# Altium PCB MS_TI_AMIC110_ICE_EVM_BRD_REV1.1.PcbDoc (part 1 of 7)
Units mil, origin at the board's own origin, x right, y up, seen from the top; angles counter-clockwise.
Board outline 3464.57 x 2204.72 mil, 8 copper layers (TopLayer - S1 (.GTL), MidLayer1 - S2 (.G1), MidLayer2 - S3 (.G2), MidLayer3 - S4 (.G3), MidLayer4 - S5 (.G4), MidLayer5 - S6 (.G5), MidLayer6 - S7 (.G6), BottomLayer - S8 (.GBL)), stack 58.937 mil thick; 504 components, 369 nets, 1811 pads, 874 vias.
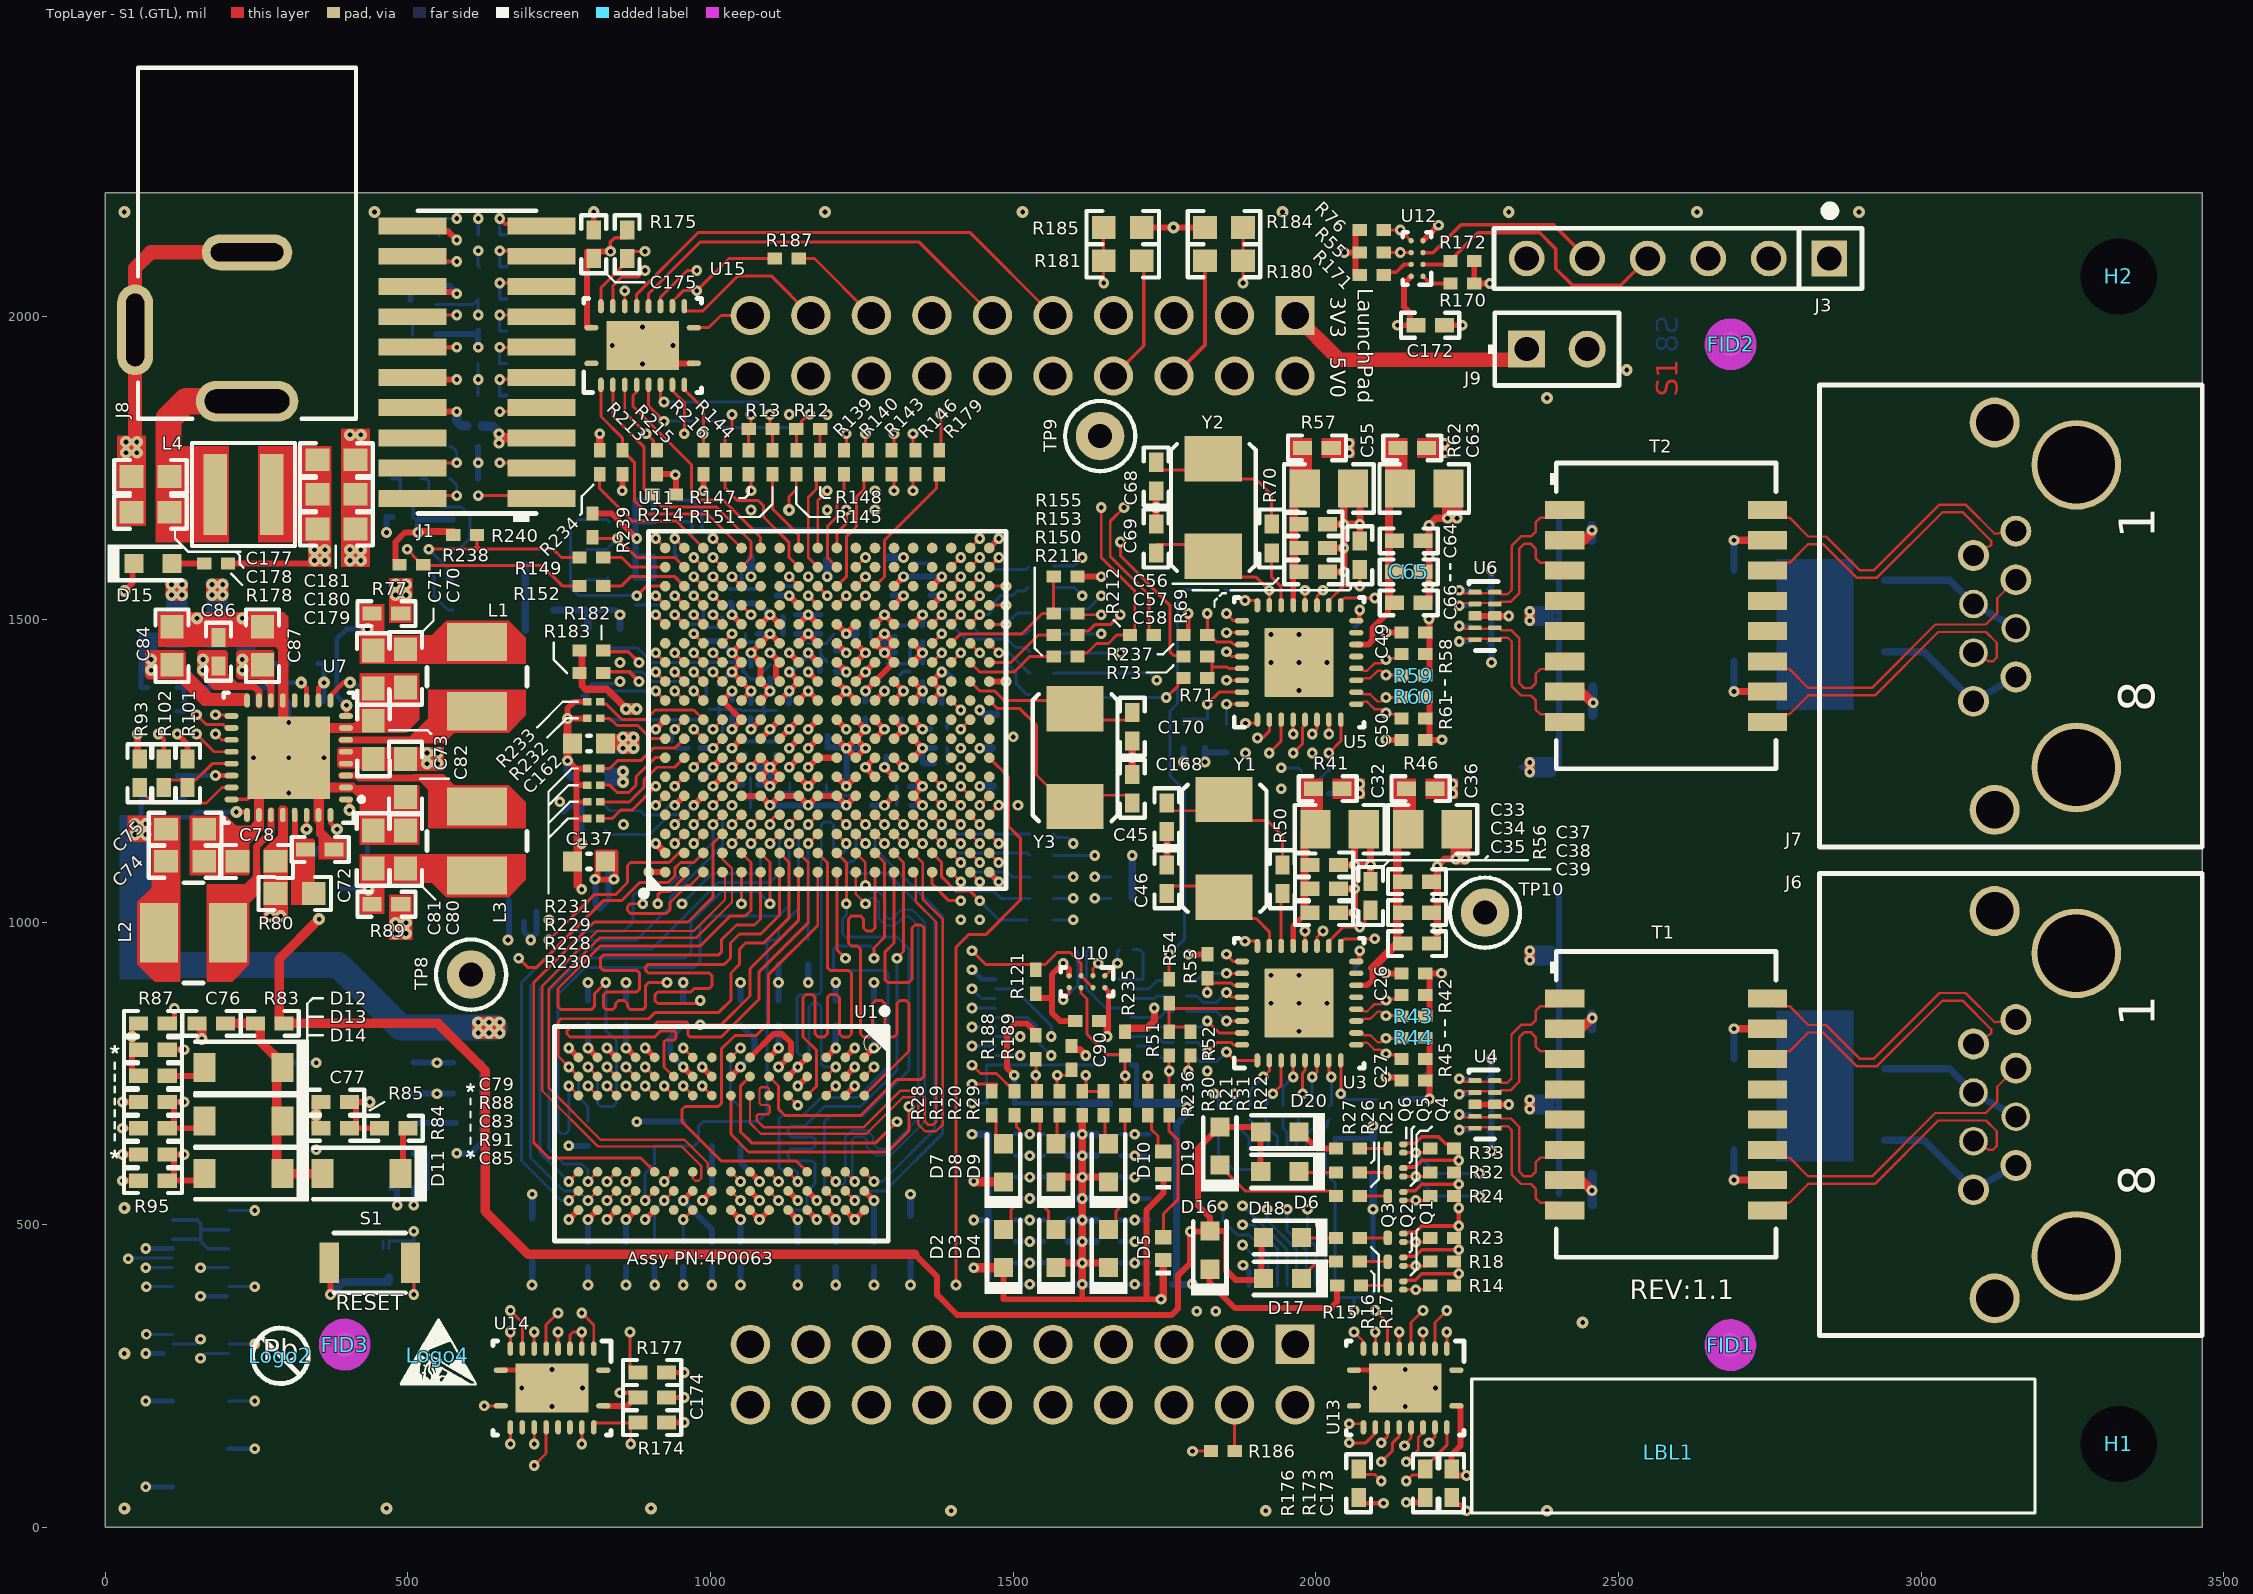
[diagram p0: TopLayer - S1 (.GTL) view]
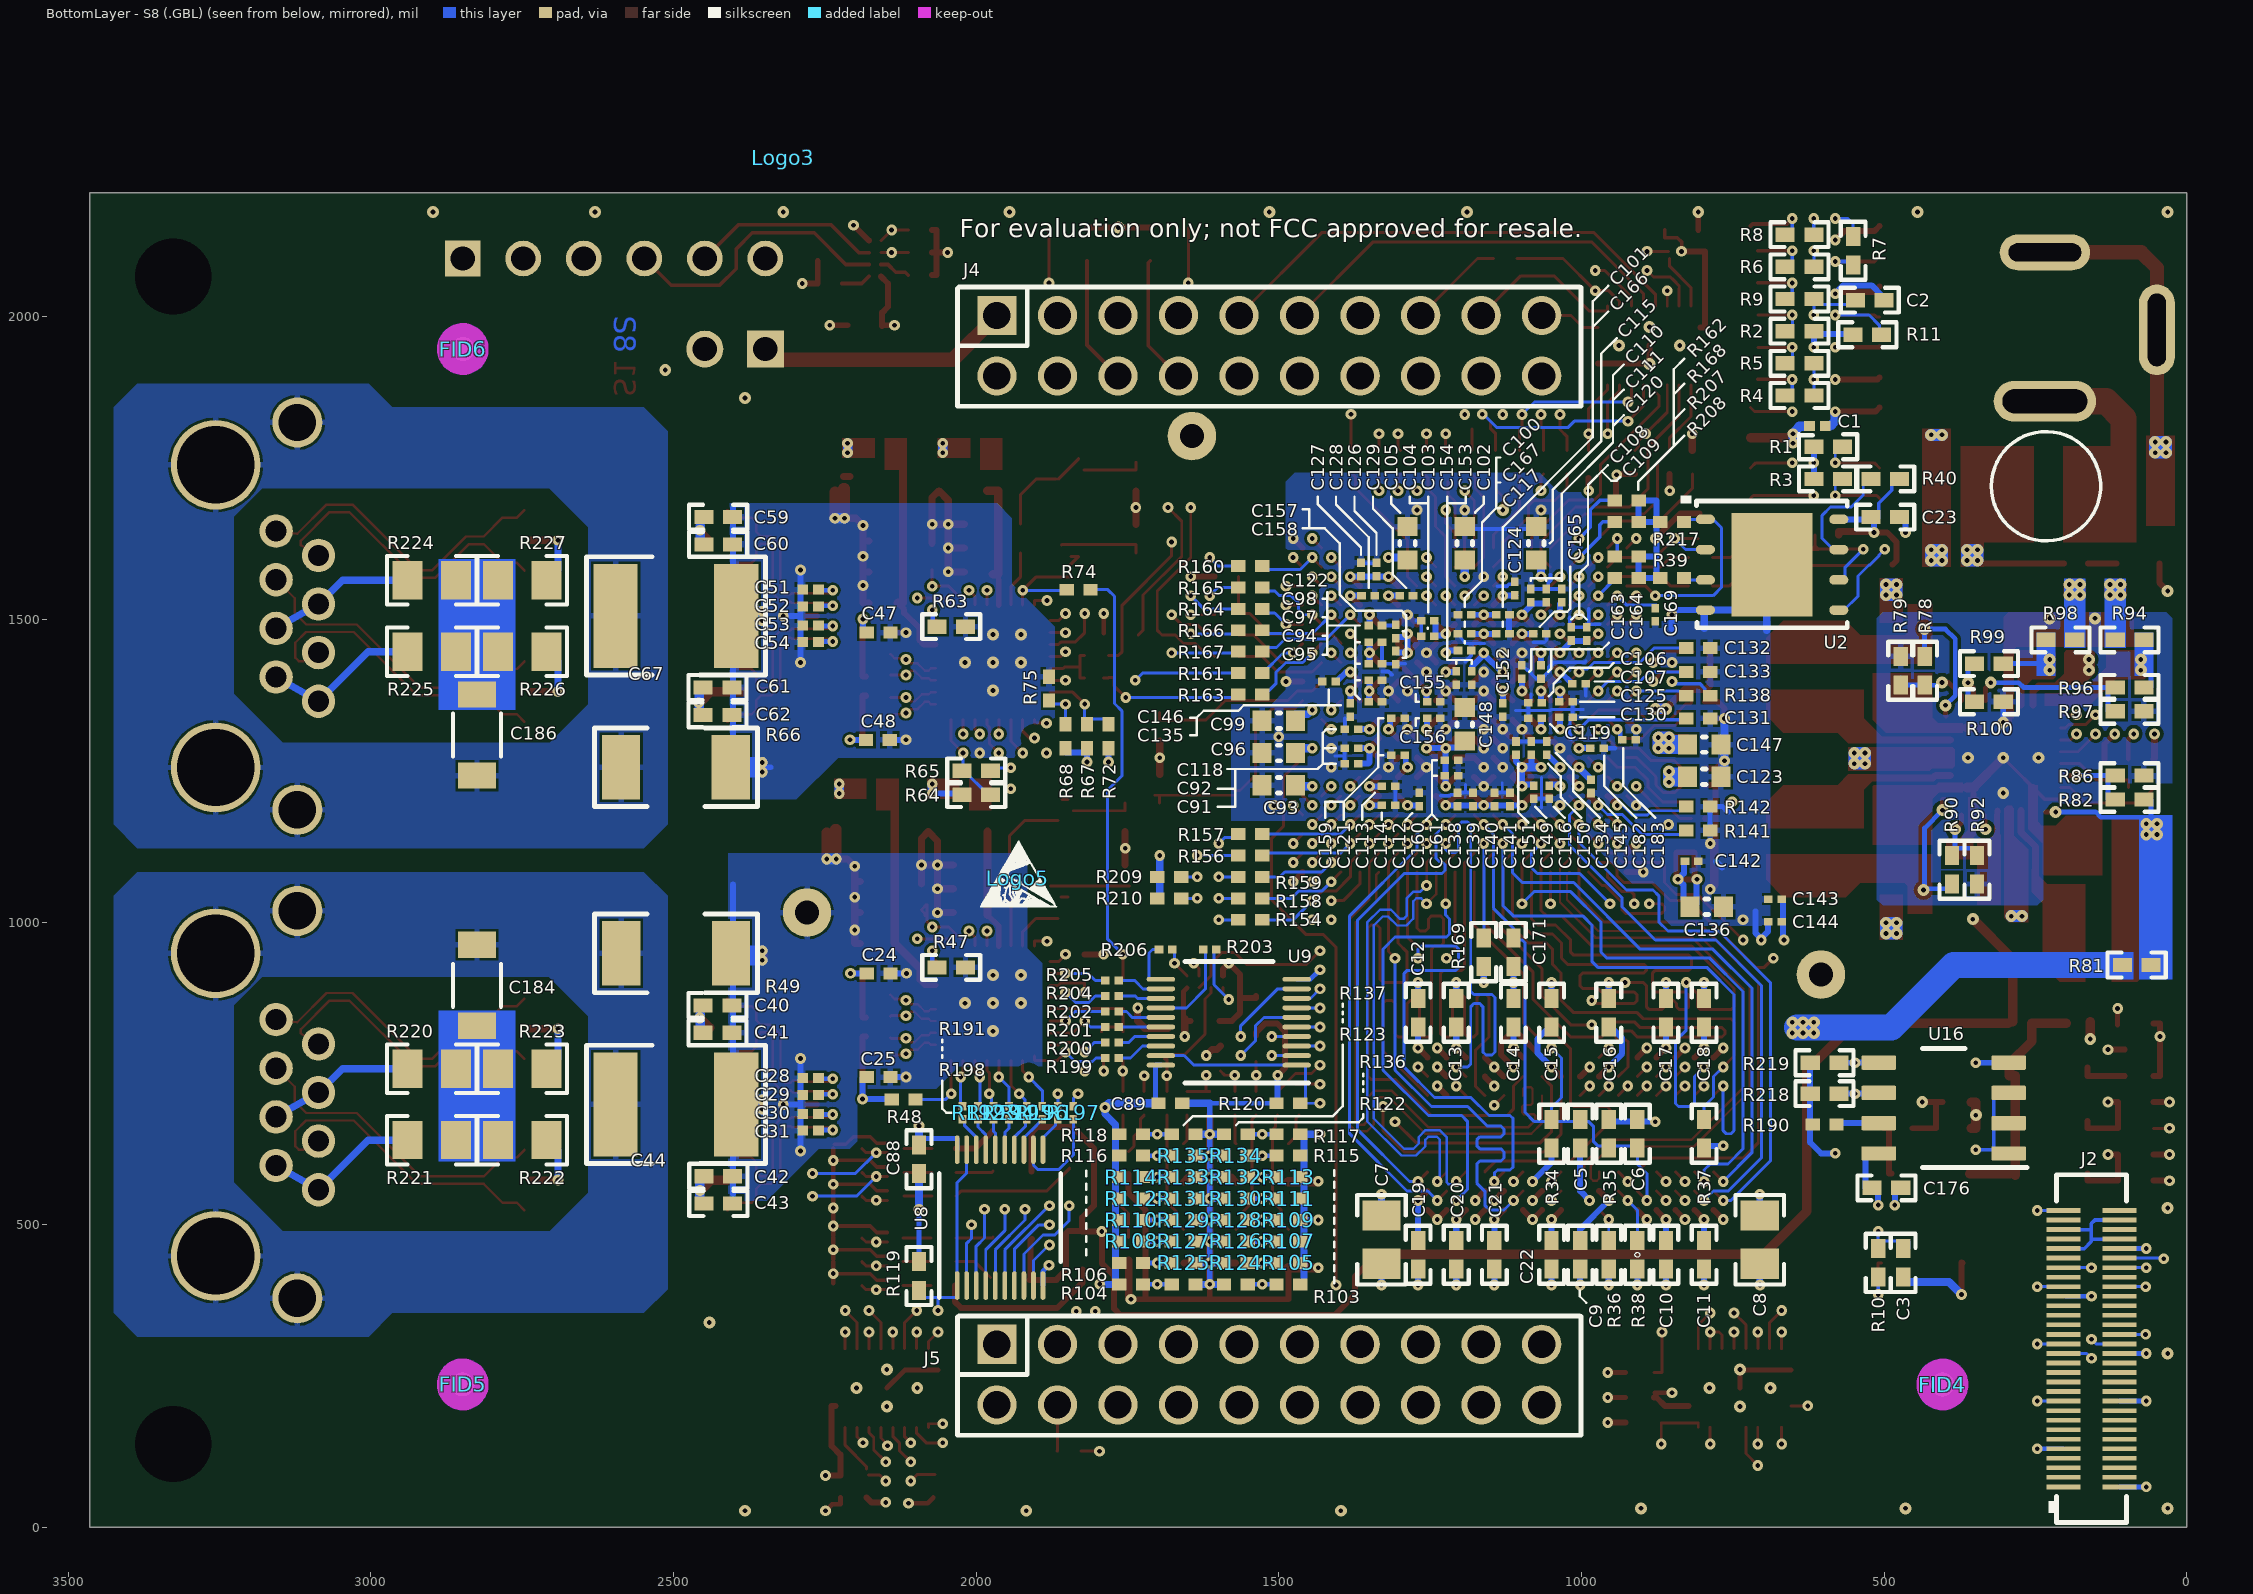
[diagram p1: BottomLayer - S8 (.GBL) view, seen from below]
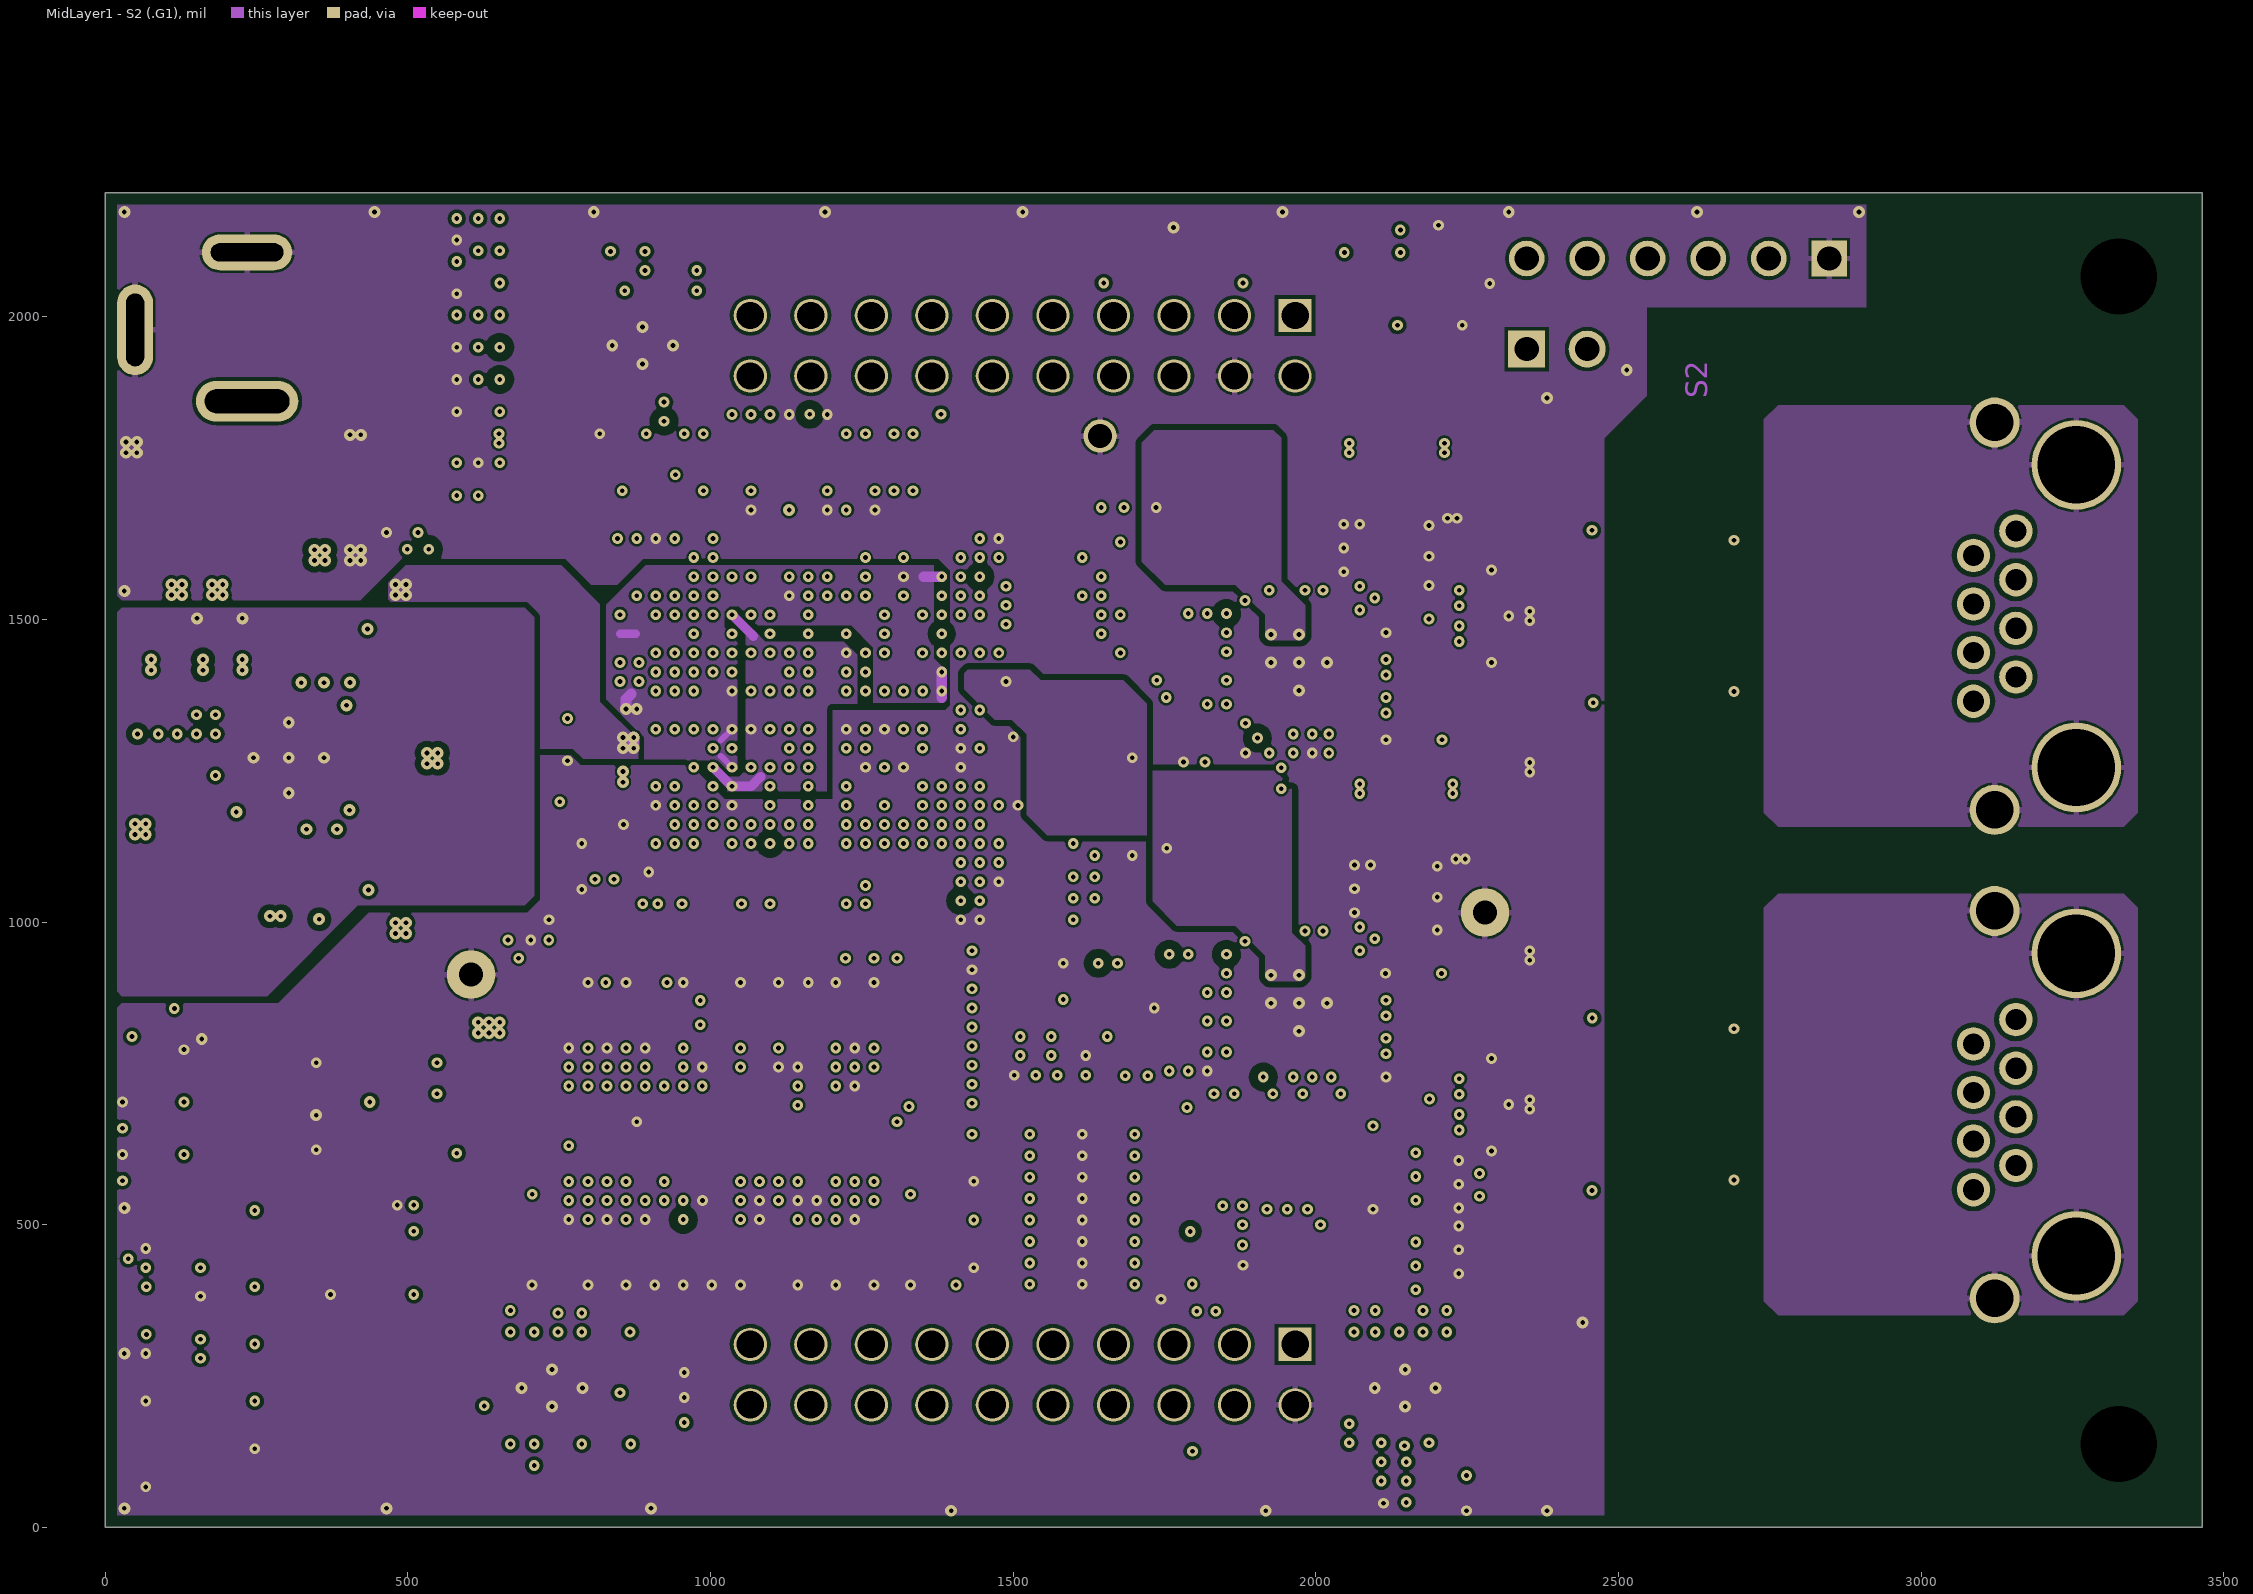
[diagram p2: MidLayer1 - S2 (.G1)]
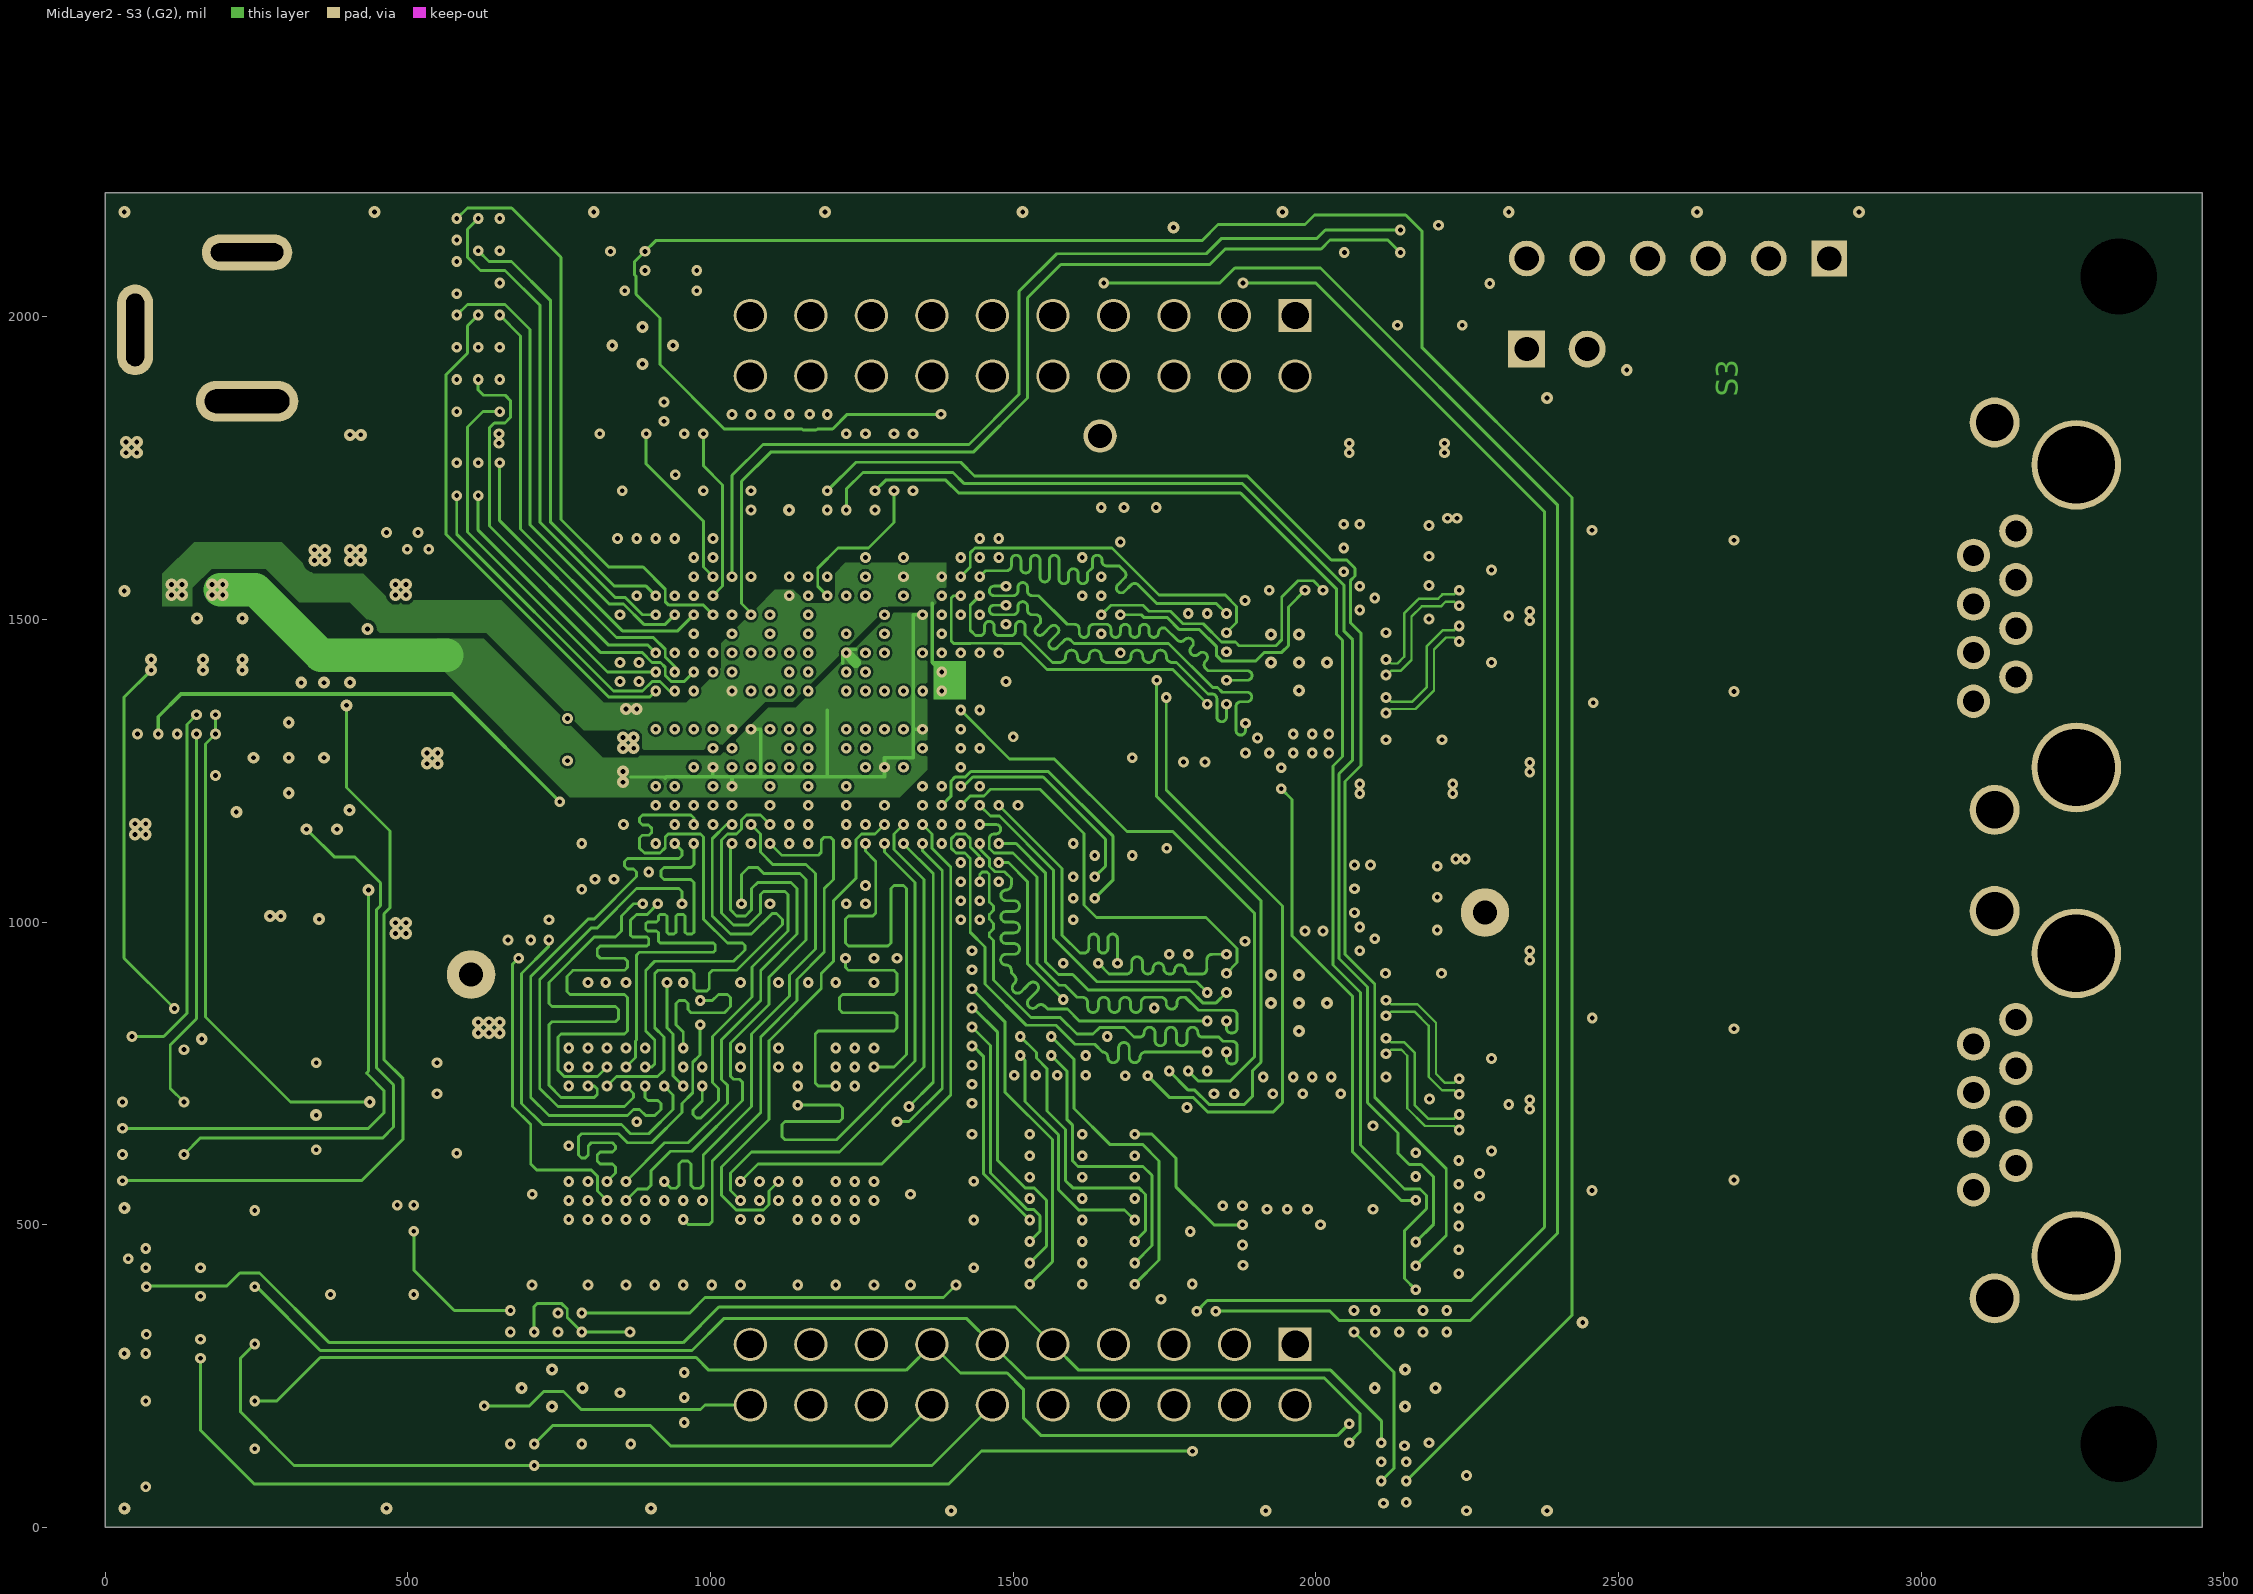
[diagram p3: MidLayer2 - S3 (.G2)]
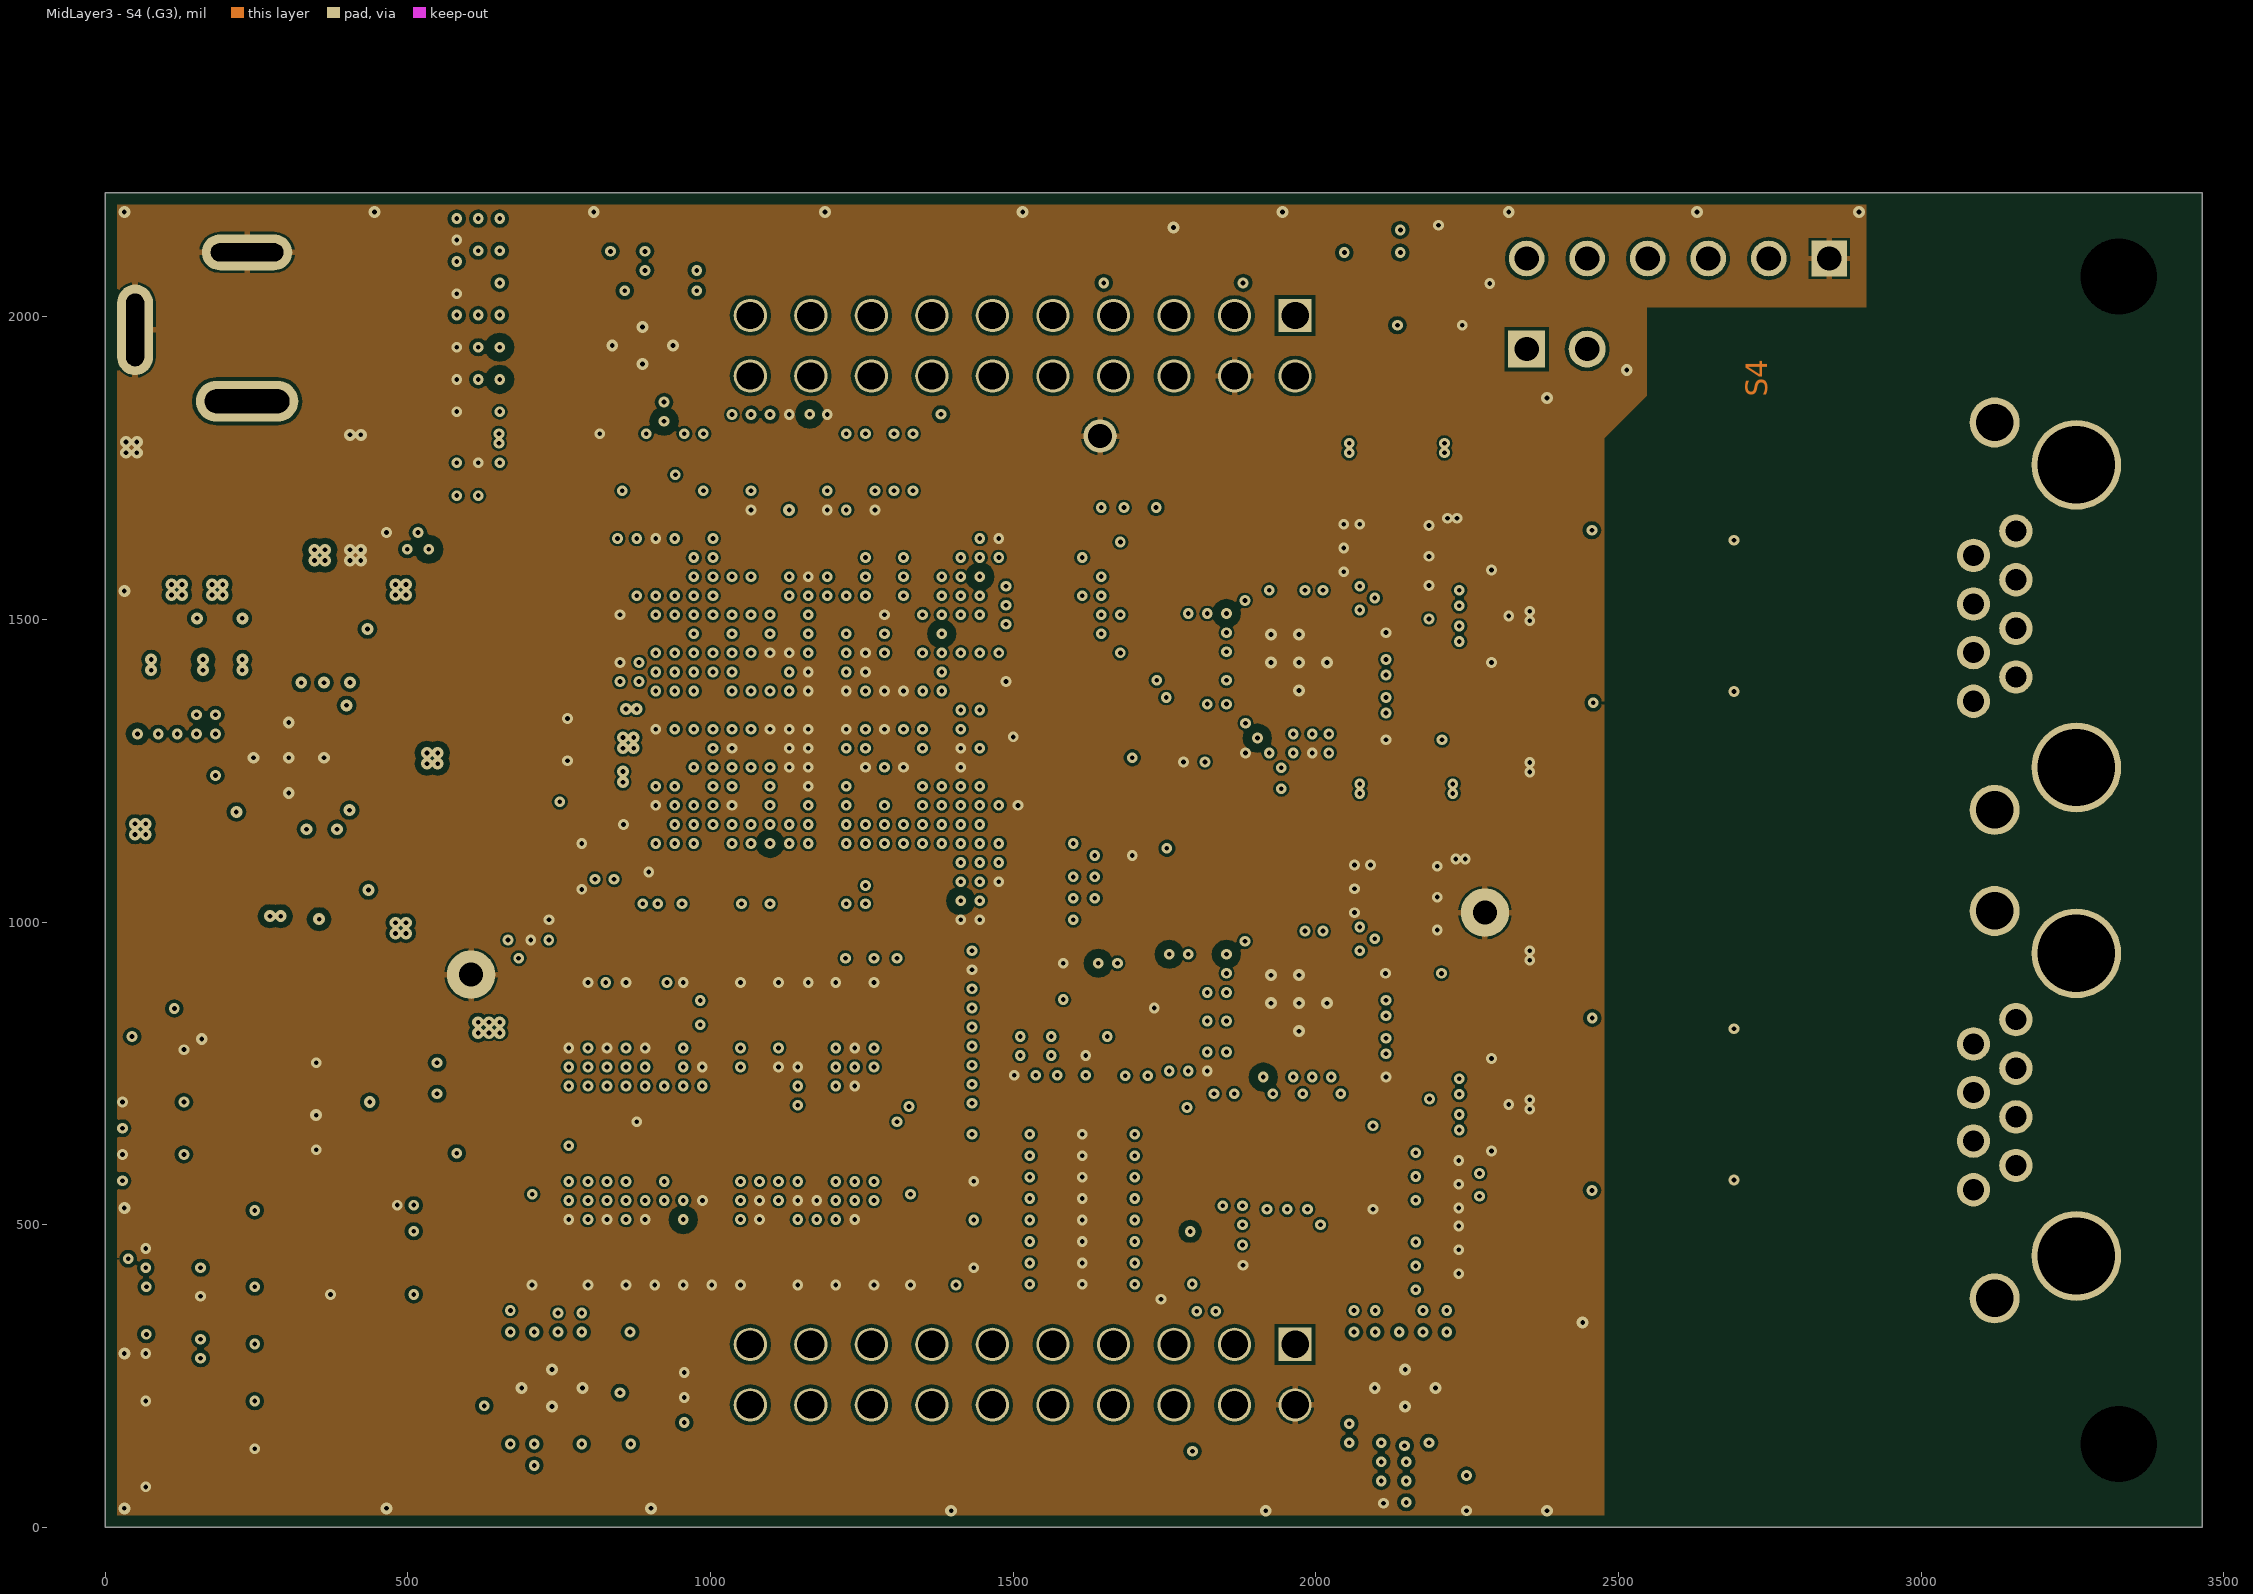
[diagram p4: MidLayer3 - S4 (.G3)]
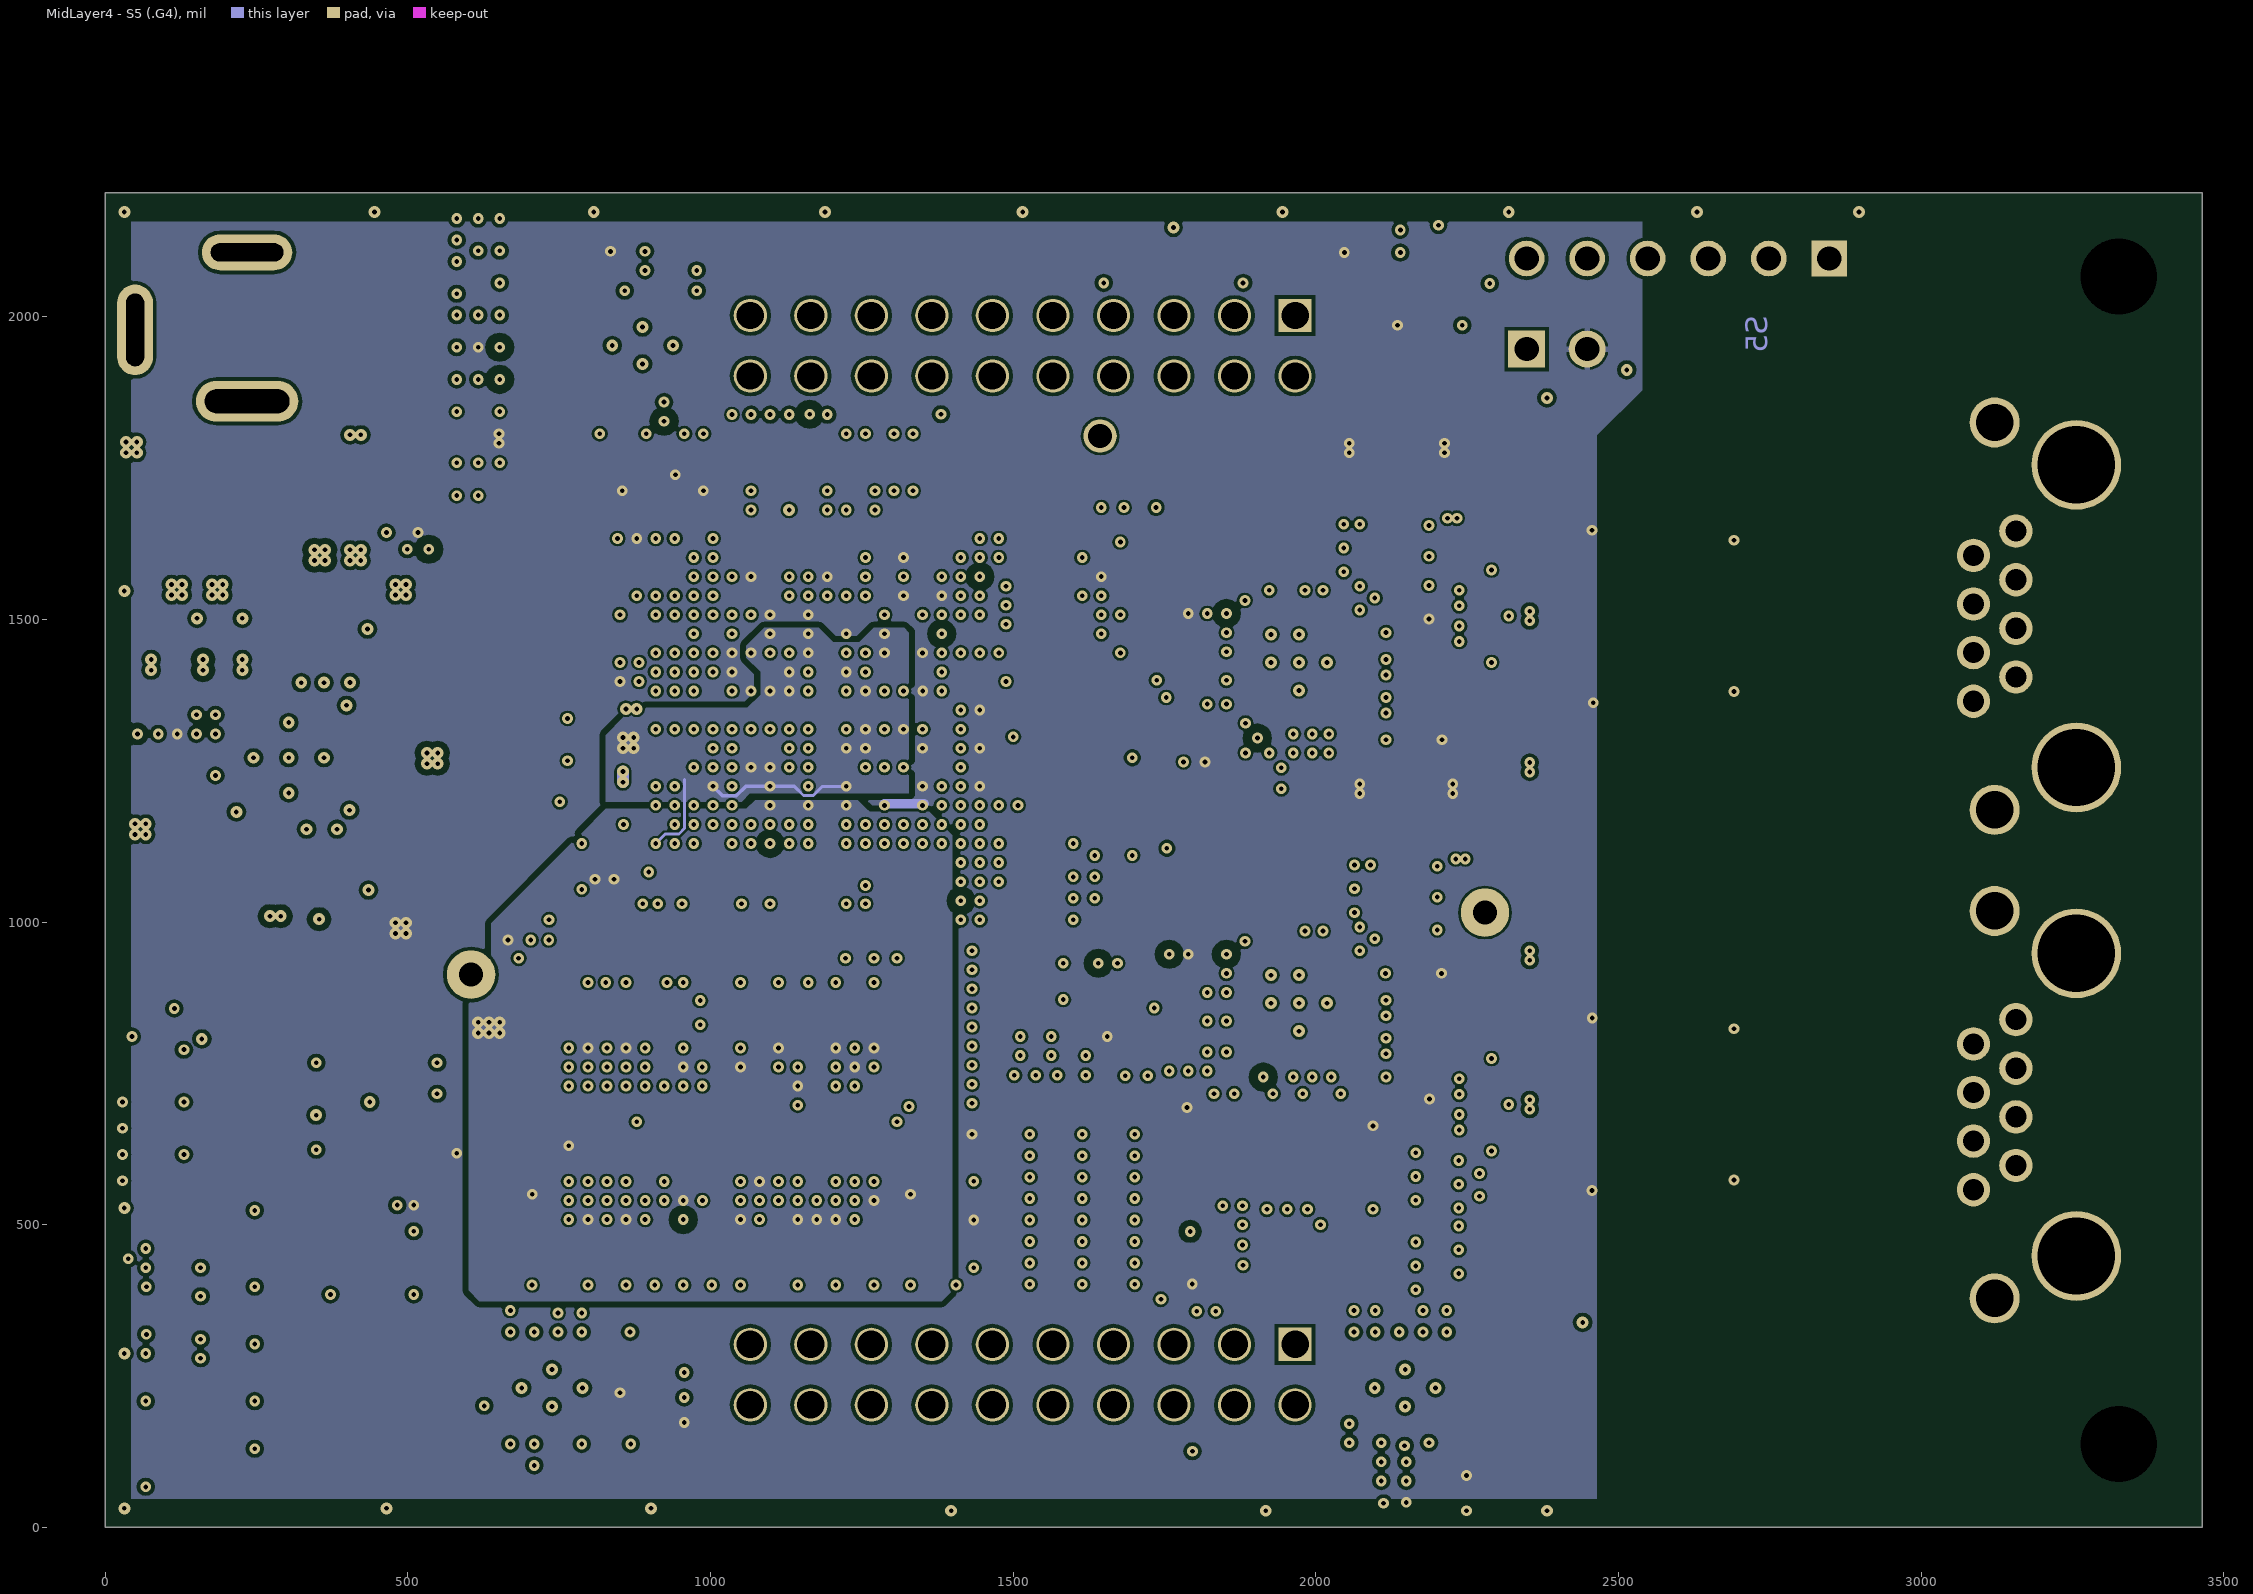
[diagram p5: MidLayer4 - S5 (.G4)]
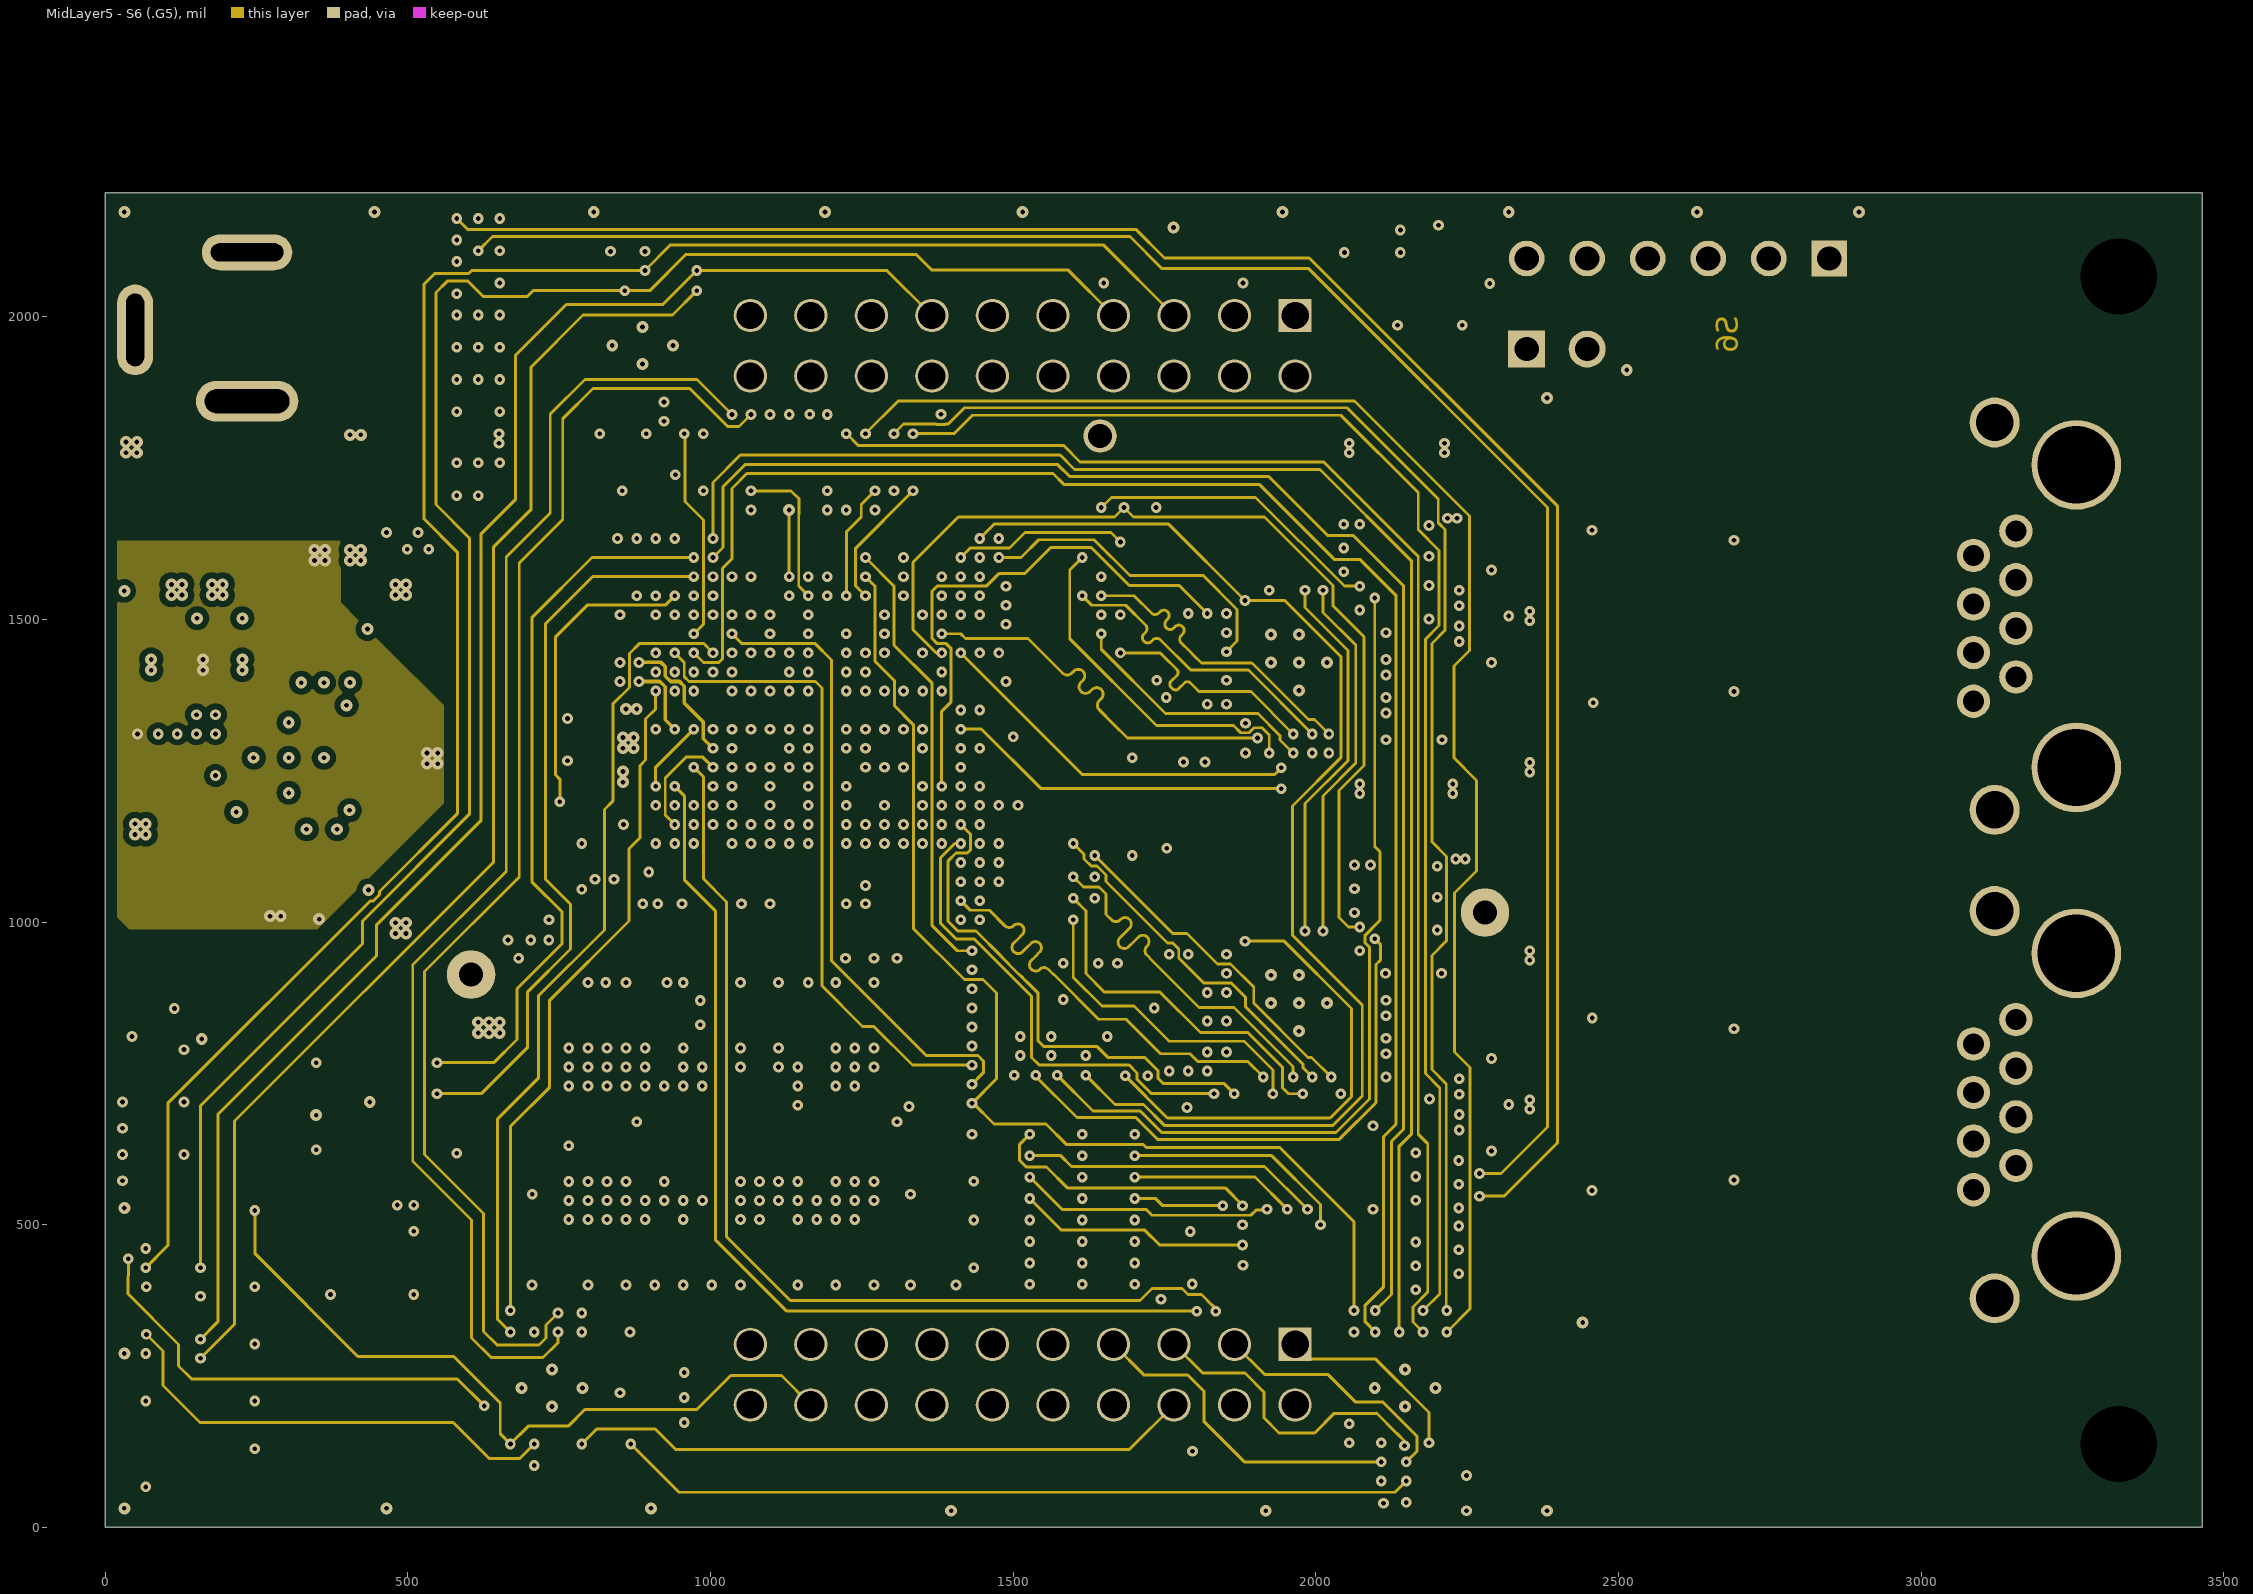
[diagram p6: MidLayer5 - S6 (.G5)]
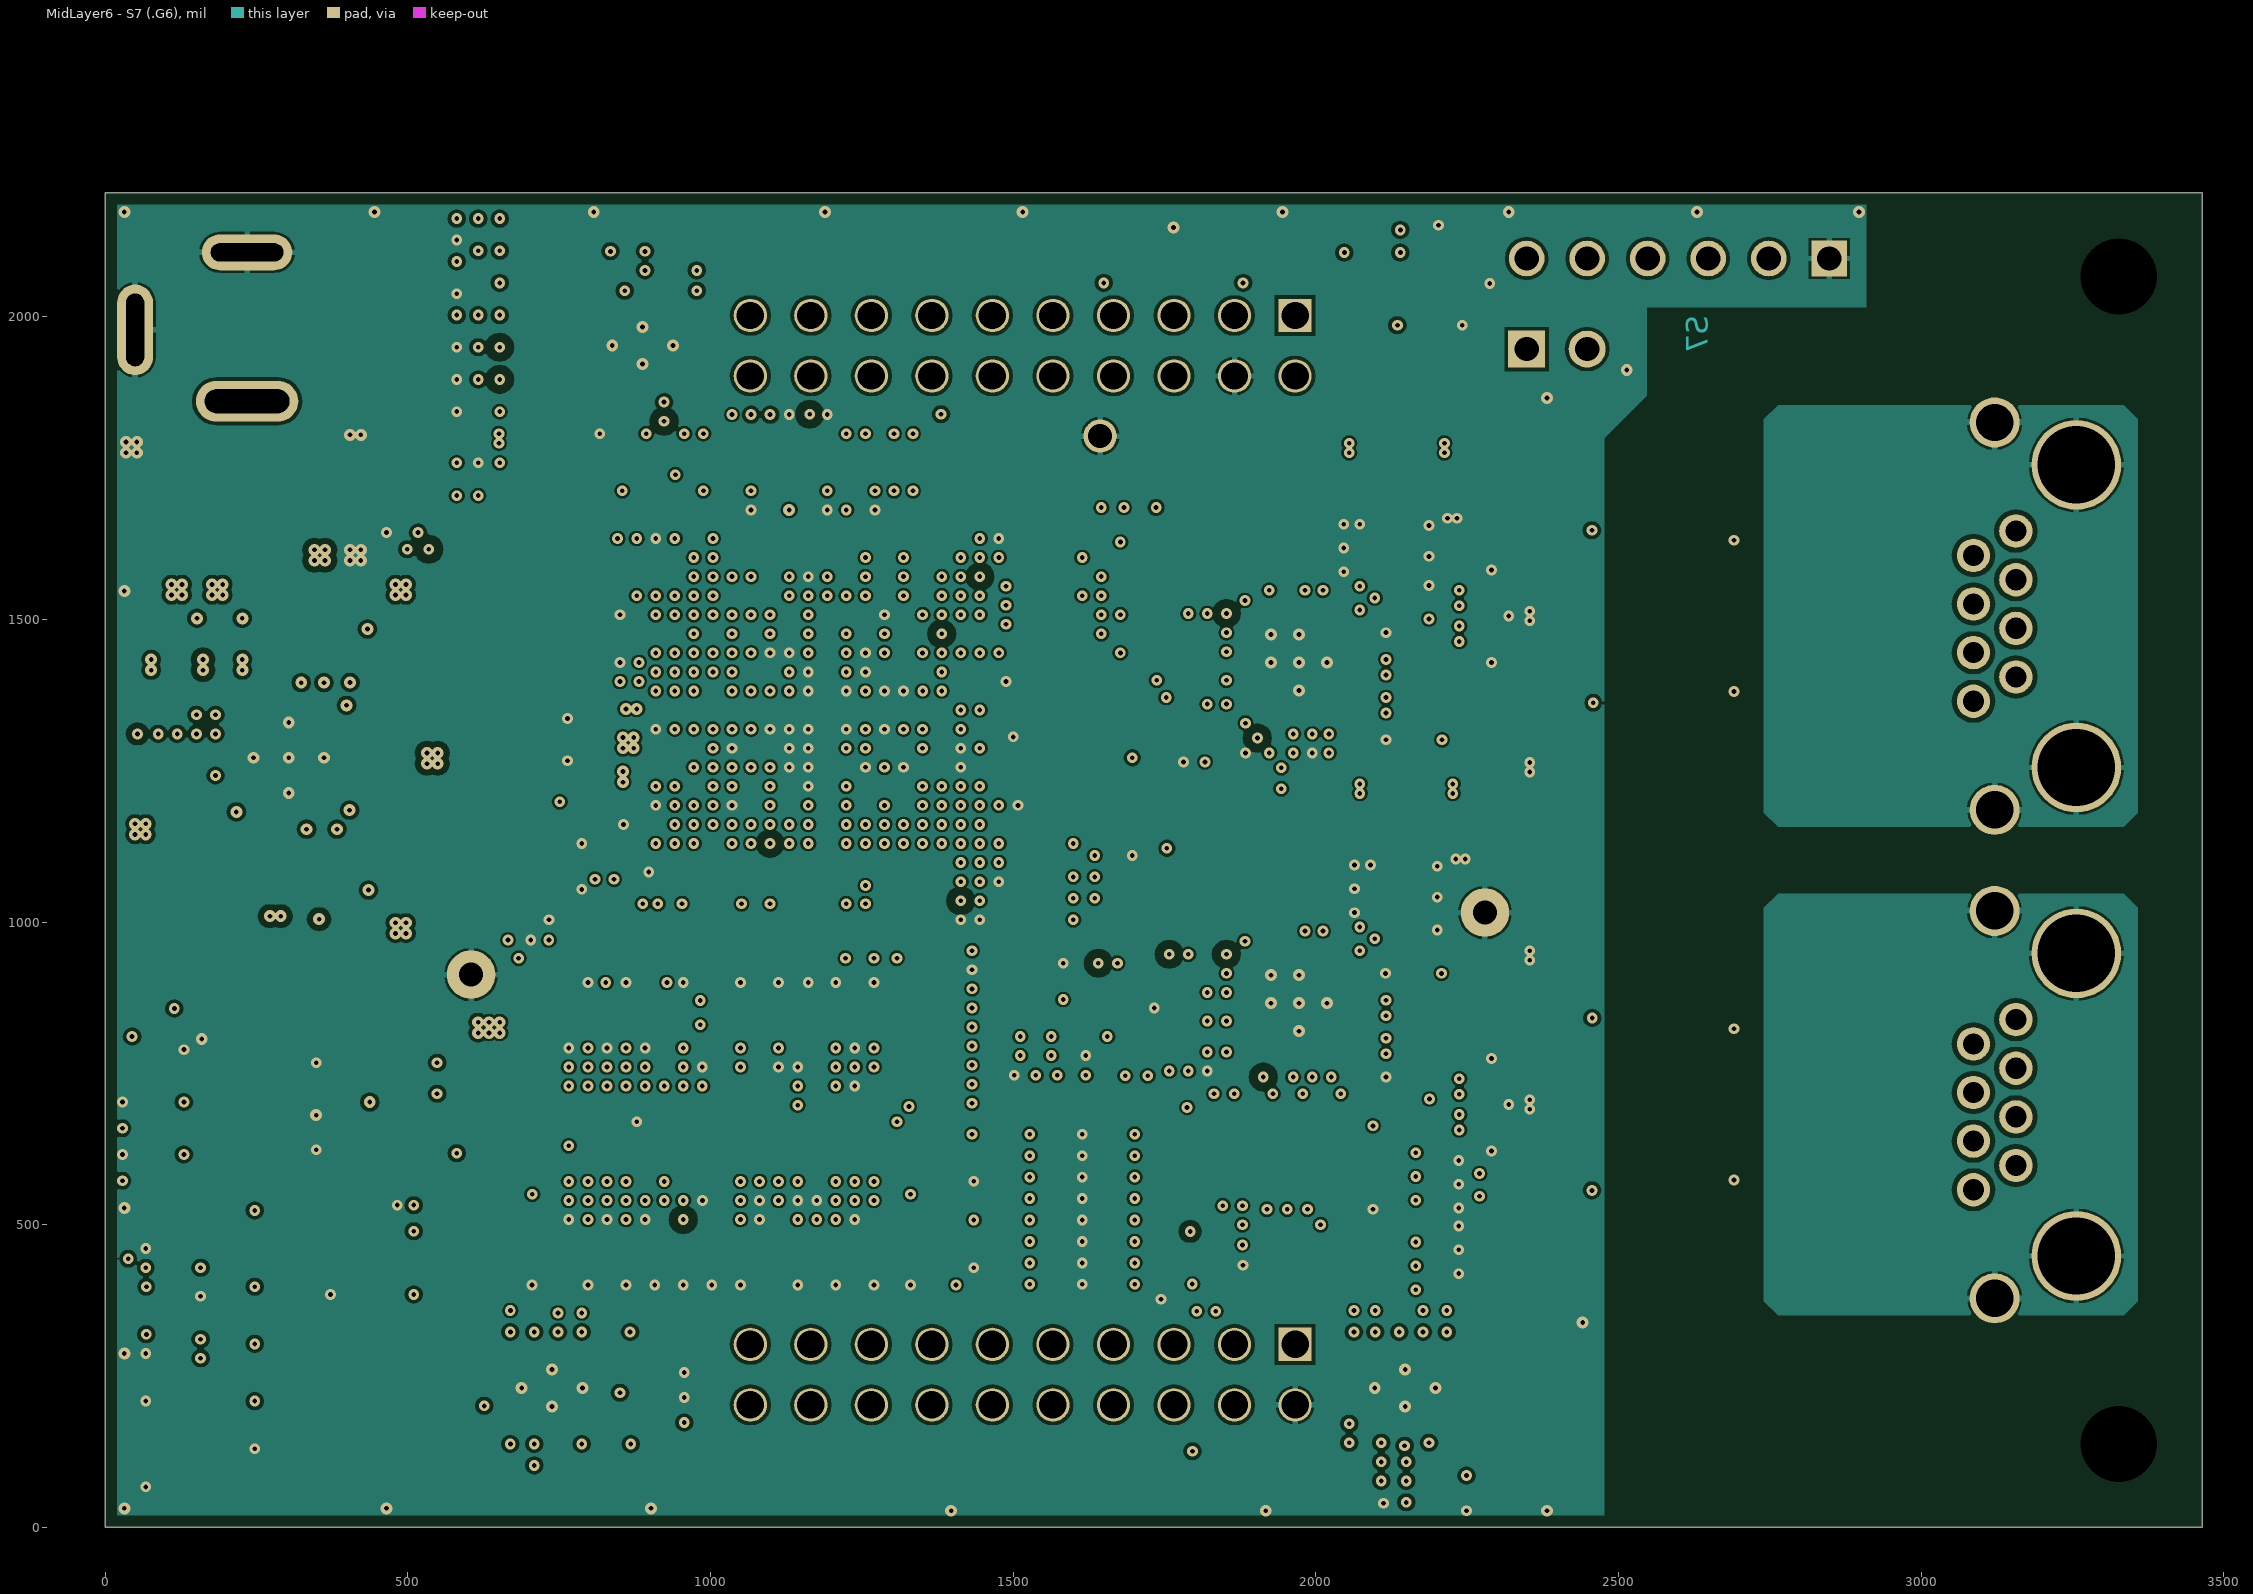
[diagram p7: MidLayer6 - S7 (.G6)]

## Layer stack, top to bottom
Top Solder: solder mask 0.5906, Solder Resist, Dk 3.9
TopLayer - S1 (.GTL): signal copper 0.7087
Dielectric1: prepreg 3.3465, FR4, IS420ML, 1x 1080 (Prepreg), Dk 4.36
MidLayer1 - S2 (.G1): signal copper 0.7087
Dielectric2: core 3.9764, FR4, IS420ML, 1x 2116 (Core), Dk 4.72
MidLayer2 - S3 (.G2): signal copper 0.7087
Dielectric3: prepreg 17.3228, FR4, IS420ML, 3x 2157 (Prepreg), Dk 4.75
MidLayer3 - S4 (.G3): signal copper 0.7087
Dielectric4: core 3.9764, FR4, IS420ML, 1x 2116 (Core), Dk 4.72
MidLayer4 - S5 (.G4): signal copper 0.7087
Dielectric5: prepreg 17.3228, FR4, IS420ML, 3x 2157 (Prepreg), Dk 4.75
MidLayer5 - S6 (.G5): signal copper 0.7087
Dielectric6: core 3.9764, FR4, IS420ML, 1x 2116 (Core), Dk 4.72
MidLayer6 - S7 (.G6): signal copper 0.7087
Dielectric7: prepreg 3.3465, FR4, IS420ML, 1x 1080 (Prepreg), Dk 4.36
BottomLayer - S8 (.GBL): signal copper 0.7087
Bottom Solder: solder mask 0.5906, Solder Resist, Dk 3.9

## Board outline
0,0 3464.57,0 3464.57,2204.72 0,2204.72

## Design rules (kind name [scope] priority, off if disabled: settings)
AcuteAngle [All] p1: minimum=4.50000000000000E+0001 checktracksonly=FALSE
AssemblyTestPointUsage [All] p1: valid=2
Clearance Clearance_Fiducial [((Component =FID1) or (Component =FID2) or (Component =FID3) or (Component =FID4) or (Component =FID5) or (Component =FID6) or ((ObjectKind = 'Component') And (Name = 'Logo1')))] p1: gap=0 ignorepadtopadclearanceinfootprint=FALSE
Clearance Clearance_BoardEdge_MountingHoles [OnCopper and InComponentClass('Mounting Holes') vs IsKeepOut  and not ((ObjectKind = 'Arc') And (AsMils(Width) = 0.5) And (Keepout = 'True'))] p2: gap=40 ignorepadtopadclearanceinfootprint=FALSE except(0: Arc-Hole Track-Hole SMDPad-Hole THPad-Hole Via-Hole Fill-Hole Poly-Hole Region-Hole Text-Hole)
Clearance Clearance_toEARTH [All vs InNet('ETH1_EARTH','ETH2_EARTH')] p3: gap=7.87 ignorepadtopadclearanceinfootprint=FALSE except(0: Arc-Hole Track-Hole SMDPad-Hole THPad-Hole Via-Hole Fill-Hole Poly-Hole Region-Hole Text-Hole)
Clearance Clearance_All-to-MountingHoles [(ObjectKind = 'Pad') And (Layer = 'MultiLayer') And (AsMM(HoleDiameter) = 3.2) And (PadIsPlated = 'True')] p4: gap=23.62 ignorepadtopadclearanceinfootprint=FALSE except(0: Arc-Hole Track-Hole SMDPad-Hole THPad-Hole Via-Hole Fill-Hole Poly-Hole Region-Hole Text-Hole)
Clearance "Clearance_to NDKs" [(ObjectKind = 'Pad') And (PadIsPlated = 'False') And (AsMM(PadXSize_AllLayers) = 0.1) And (AsMM(PadYSize_AllLayers) = 0.1)] p5 off: gap=19.68 ignorepadtopadclearanceinfootprint=FALSE except(0: Arc-Hole Track-Hole SMDPad-Hole THPad-Hole Via-Hole Fill-Hole Poly-Hole Region-Hole Text-Hole)
Clearance Clearance_Keepouts [((IsTrack Or IsArc) And Not InPoly) And IsFree and IsKeepOut vs ((IsTrack Or IsArc) And Not InPoly) And IsFree and IsKeepOut] p6: gap=0 ignorepadtopadclearanceinfootprint=FALSE
Clearance Clearance_BoardEdge_Poly [OnCopper and InPoly vs IsKeepOut  and not ((ObjectKind = 'Arc') And (AsMils(Width) = 0.5) And (Keepout = 'True'))] p7: gap=25 ignorepadtopadclearanceinfootprint=FALSE except(0: Arc-Hole Track-Hole SMDPad-Hole THPad-Hole Via-Hole Fill-Hole Poly-Hole Region-Hole Text-Hole)
Clearance Clearance_BoardEdge [OnCopper and Not InComponentClass('Logo') and not InComponentClass('FiducialMark') and not InRegion(1000,500,4000,800) and Not IsKeepout vs IsKeepOut  and not ((ObjectKind = 'Arc') And (AsMils(Width) = 0.5) And (Keepout = 'True'))] p8: gap=19.6 ignorepadtopadclearanceinfootprint=FALSE except(0: Arc-Hole Track-Hole SMDPad-Hole THPad-Hole Via-Hole Fill-Hole Poly-Hole Region-Hole Text-Hole)
Clearance Clearance_CLKs [InNetClass('CLKs')  and not OnBottom vs All and not (WithinRoom('AMIC110 ICE EVM_Power') or IsVia or IsSMTPin)] p9: gap=14.76 ignorepadtopadclearanceinfootprint=FALSE except(0: Arc-Hole Track-Hole SMDPad-Hole THPad-Hole Via-Hole Fill-Hole Poly-Hole Region-Hole Text-Hole)
Clearance Clearance_PWR [InNetClass('PWR') and not OnTop vs InNetClass('PWR')] p10 off: gap=9.84 ignorepadtopadclearanceinfootprint=FALSE except(0: Arc-Hole Track-Hole SMDPad-Hole THPad-Hole Via-Hole Fill-Hole Poly-Hole Region-Hole Text-Hole)
Clearance Clearance_to-VIN5V [InNet('VIN5V') vs all and not (OnTop or OnBottom)] p11: gap=9.84 ignorepadtopadclearanceinfootprint=FALSE except(0: Arc-Hole Track-Hole SMDPad-Hole THPad-Hole Via-Hole Fill-Hole Poly-Hole Region-Hole Text-Hole)
Clearance Clearance_Poly-to-Poly [InPolygon vs InPolygon] p12: gap=9.84 ignorepadtopadclearanceinfootprint=FALSE except(0: Arc-Hole Track-Hole SMDPad-Hole THPad-Hole Via-Hole Fill-Hole Poly-Hole Region-Hole Text-Hole)
Clearance "Clearance_BGA 0.8mm_BottomLayer&Poly" [WithinRoom('AMIC110 ICE EVM_Power') and OnBottomLayer] p13: gap=3.94 ignorepadtopadclearanceinfootprint=FALSE except(0: Arc-Hole Track-Hole SMDPad-Hole THPad-Hole Via-Hole Fill-Hole Poly-Hole Region-Hole Text-Hole)
Clearance "Clearance_BGA 0.8mm" [WithinRoom('AMIC110 ICE EVM_Power')] p14: gap=3.94 ignorepadtopadclearanceinfootprint=FALSE except(0: Arc-Hole Track-Hole SMDPad-Hole THPad-Hole Via-Hole Fill-Hole Poly-Hole Region-Hole Text-Hole)
Clearance [All] p15: gap=5.91 ignorepadtopadclearanceinfootprint=FALSE except(0: Arc-Hole Track-Hole SMDPad-Hole THPad-Hole Via-Hole Fill-Hole Poly-Hole Region-Hole Text-Hole)
Clearance Clearance_Poly [InPolygon vs All and not (OnBottomLayer or OnTopLayer)] p16 off: gap=25 ignorepadtopadclearanceinfootprint=FALSE except(0: Arc-Hole Track-Hole SMDPad-Hole THPad-Hole Via-Hole Fill-Hole Poly-Hole Region-Hole Text-Hole)
ComponentClearance ComponentClearance_MountingHoles_FiducialMarks [InComponentClass('Mounting Holes') vs InComponentClass('FiducialMark')] p1 off: gap=50 collisioncheckmode=3 verticalgap=10 showdistances=FALSE
ComponentClearance ComponentClearance_Shunt [InComponentClass('Header') vs InComponentClass('Shunt')] p2 off: gap=0 collisioncheckmode=3 verticalgap=0 showdistances=FALSE
ComponentClearance ComponentClearance_Logo [InComponentClass('Logo')] p3 off: gap=50 collisioncheckmode=3 verticalgap=10 showdistances=FALSE
ComponentClearance ComponentClearance_ScrewToNut [(HasFootprint('NY PMS 440 0025 PH')) vs (HasFootprint('Keystone_1902C'))] p4 off: gap=5 collisioncheckmode=3 verticalgap=10 showdistances=FALSE
ComponentClearance ComponentClearance_MountingHoles [InComponentClass('Mounting Holes')] p5 off: gap=250 collisioncheckmode=3 verticalgap=100000 showdistances=FALSE
ComponentClearance ComponentClearance_SmallPassives [HasFootprint('0402') or HasFootprint('*0508') or HasFootprint('*0603*') or HasFootprint('*0612') or HasFootprint('*0805*') or HasFootprint('*0815*') or HasFootprint('*0830*') or HasFootprint('*1206*') or HasFootprint('*1210*') or HasFootprint('*1808*') or HasFootprint('*1812*') or HasFootprint('*1825*') or HasFootprint('*2010*') or HasFootprint('*2220*') or HasFootprint('*2225*') or HasFootprint('*2512*') or HasFootprint('*2728*') or HasFootprint('*3518*') vs HasFootprint('0402') or HasFootprint('*0508') or HasFootprint('*0603*') or HasFootprint('*0612') or HasFootprint('*0805*') or HasFootprint('*0815*') or HasFootprint('*0830*') or HasFootprint('*1206*') or HasFootprint('*1210*') or HasFootprint('*1808*') or HasFootprint('*1812*') or HasFootprint('*1825*') or HasFootprint('*2010*') or HasFootprint('*2220*') or HasFootprint('*2225*') or HasFootprint('*2512*') or HasFootprint('*2728*') or HasFootprint('*3518*')] p6: gap=15.75 collisioncheckmode=3 verticalgap=10 showdistances=TRUE
ComponentClearance ComponentClearance_0201+0402L [HasFootprint('0402L') or HasFootprint('*0201*') vs HasFootprint('0402L') or HasFootprint('*0201*')] p7: gap=11.81 collisioncheckmode=3 verticalgap=10 showdistances=TRUE
ComponentClearance ComponentClearance_THtoSMT [IsThruComponent vs IsSMTComponent and OnBottom] p8 off: gap=100 collisioncheckmode=3 verticalgap=30 showdistances=FALSE
ComponentClearance ComponentClearance_THtoTH [IsThruComponent vs IsThruComponent] p9 off: gap=118.11 collisioncheckmode=3 verticalgap=30 showdistances=FALSE
ComponentClearance [All] p10 off: gap=10 collisioncheckmode=3 verticalgap=10 showdistances=FALSE
ComponentClearance ComponentClearance_NoOverlapping [All and not InComponent('J5','J6','Logo*','FID*') vs All and not InComponent('J5','J6','Logo*','FID*')] p11: gap=11.81 collisioncheckmode=3 verticalgap=10 showdistances=FALSE
DiffPairsRouting DiffPairs_100R [InDifferentialPairClass('Zdiff=100R')] p1: maxlimit=11.81 minlimit=8.27 mostfreqgap=8.27 toplayer_mingap=8.46 toplayer_prefgap=8.46 toplayer_minwidth=3.98 toplayer_maxwidth=15 toplayer_prefwidth=3.98 midlayer1_maxgap=10 midlayer1_minwidth=3.98 midlayer1_maxwidth=15 midlayer1_prefwidth=3.98 midlayer2_maxgap=10 midlayer2_minwidth=3.98 midlayer2_maxwidth=15 midlayer2_prefwidth=3.98 midlayer3_maxgap=10 midlayer3_minwidth=3.98 midlayer3_maxwidth=15 midlayer3_prefwidth=3.98 midlayer4_maxgap=10 midlayer4_minwidth=3.98 midlayer4_maxwidth=15 midlayer4_prefwidth=3.98 midlayer5_maxgap=10 midlayer5_minwidth=3.98 midlayer5_maxwidth=15 midlayer5_prefwidth=3.98 midlayer6_maxgap=10 midlayer6_minwidth=3.98 midlayer6_maxwidth=15 midlayer6_prefwidth=3.98 bottomlayer_mingap=8.46 bottomlayer_maxgap=10 bottomlayer_prefgap=8.46 bottomlayer_minwidth=3.98 bottomlayer_maxwidth=15 bottomlayer_prefwidth=3.98 maxuncoupledlength=1259.84
DiffPairsRouting DiffPairs_90R [InDifferentialPairClass('Zdiff=90R')] p2: maxlimit=10 minlimit=8.27 mostfreqgap=8.27 toplayer_minwidth=5.12 toplayer_maxwidth=15 toplayer_prefwidth=5.12 midlayer1_minwidth=5.12 midlayer1_maxwidth=15 midlayer1_prefwidth=5.12 midlayer2_minwidth=5.12 midlayer2_maxwidth=15 midlayer2_prefwidth=5.12 midlayer3_minwidth=5.12 midlayer3_maxwidth=15 midlayer3_prefwidth=5.12 midlayer4_minwidth=5.12 midlayer4_maxwidth=15 midlayer4_prefwidth=5.12 midlayer5_minwidth=5.12 midlayer5_maxwidth=15 midlayer5_prefwidth=5.12 midlayer6_minwidth=5.12 midlayer6_maxwidth=15 midlayer6_prefwidth=5.12 bottomlayer_minwidth=5.12 bottomlayer_maxwidth=15 bottomlayer_prefwidth=5.12 maxuncoupledlength=200
DiffPairsRouting [All] p3 off: maxlimit=100 minlimit=10 mostfreqgap=10 toplayer_minwidth=15 toplayer_maxwidth=15 toplayer_prefwidth=15 midlayer1_minwidth=15 midlayer1_maxwidth=15 midlayer1_prefwidth=15 midlayer2_minwidth=15 midlayer2_maxwidth=15 midlayer2_prefwidth=15 midlayer3_minwidth=15 midlayer3_maxwidth=15 midlayer3_prefwidth=15 midlayer4_minwidth=15 midlayer4_maxwidth=15 midlayer4_prefwidth=15 midlayer5_minwidth=15 midlayer5_maxwidth=15 midlayer5_prefwidth=15 midlayer6_minwidth=15 midlayer6_maxwidth=15 midlayer6_prefwidth=15 bottomlayer_minwidth=15 bottomlayer_maxwidth=15 bottomlayer_prefwidth=15 maxuncoupledlength=1259.84
FabricationTestPointUsage TestPointUsage [All] p1: valid=2 allowmultiple=FALSE
FabricationTestpoint Testpoint [All] p1: side=3 testpointundercomponent=TRUE minsize=40 maxsize=100 preferedsize=60 minholesize=0 maxholesize=40 preferedholesize=32 testpointgrid=1 allowsidetop=TRUE allowsidebottom=TRUE usegrid=TRUE gridtolerance=0.01
FanoutControl Fanout_LCC [IsLCC] p1: bgadir=Out bgaviamode=Centered fanoutstyle=Auto fanoutdirection=Alternating viagrid=1 // Fanout_LCC (Default Rule)
FanoutControl Fanout_BGA [IsBGA] p2: bgadir=Out bgaviamode=Centered fanoutstyle=Auto fanoutdirection=Alternating viagrid=1 // Fanout_BGA (Default Rule)
FanoutControl Fanout_Default [All] p4: bgadir=Out bgaviamode=Centered fanoutstyle=Auto fanoutdirection=Alternating viagrid=1 // Fanout_Default (Default Rule)
FanoutControl Fanout_Small [(CompPinCount < 5)] p5: bgadir=Out bgaviamode=Centered fanoutstyle=Auto fanoutdirection=OutThenIn viagrid=1 // Fanout_Small (Default Rule)
Height [All] p1 off: minheight=0 maxheight=1000 prefheight=500
HoleSize [All] p1: absolutevalues=TRUE maxlimit=251 minlimit=7.5 maxpercent=80.000 minpercent=20.000
HoleToHoleClearance [All] p1: gap=7.87 allowstackedmicrovias=TRUE
MatchedLengths MatchLengths_xSignals_ETH2 [InxSignalClass('xSignals_ETH2_MatchLengthsClass')] p1 off: tolerance=3.94 checknetsindiffpair=FALSE checkdiffpairvsdiffpair=TRUE checkxsignals=TRUE checkothers=TRUE
MatchedLengths MatchLengths_ETH1_U3_Passives_J6 [InxSignalClass('xSignals_ETH1_U3_Passives_J6_MatchLengthsClass')] p2: tolerance=3.94 checknetsindiffpair=FALSE checkdiffpairvsdiffpair=TRUE checkxsignals=TRUE checkothers=TRUE
MatchedLengths MatchLengths_xSignals_ETH1_U3_Passives [InxSignalClass('xSignals_ETH1_U3_Passives_MatchLengthsClass')] p3: tolerance=3.94 checknetsindiffpair=FALSE checkdiffpairvsdiffpair=TRUE checkxsignals=TRUE checkothers=TRUE
MatchedLengths MatchLengths_xSignals_ETH1_1 [InxSignalClass('xSignals_ETH1_MatchLengthsClass')] p4 off: tolerance=3.94 checknetsindiffpair=FALSE checkdiffpairvsdiffpair=TRUE checkxsignals=TRUE checkothers=TRUE
MatchedLengths MatchLengths_U3_Passives_J6 [InxSignalClass('xSignals_U3_Passives_J6_MatchLengthsClass')] p5: tolerance=7.87 checknetsindiffpair=FALSE checkdiffpairvsdiffpair=TRUE checkxsignals=TRUE checkothers=TRUE
MatchedLengths MatchLengths_xSignals_U3_Passives [InxSignalClass('xSignals_U3_Passives_MatchLengthsClass')] p6: tolerance=7.87 checknetsindiffpair=FALSE checkdiffpairvsdiffpair=TRUE checkxsignals=TRUE checkothers=TRUE
MatchedLengths MatchLengths_xSignals_ETH1 [InxSignalClass('xSignals_ETH1_MatchLengthsClass')] p7 off: tolerance=7.87 checknetsindiffpair=FALSE checkdiffpairvsdiffpair=TRUE checkxsignals=TRUE checkothers=TRUE
MatchedLengths MatchLengths_J6_Passives_U3 [InxSignalClass('xSignals_J6_Passives_U3_MatchLengthsClass')] p8: tolerance=7.87 checknetsindiffpair=FALSE checkdiffpairvsdiffpair=TRUE checkxsignals=TRUE checkothers=TRUE
MatchedLengths MatchLengths_xSignals_PHY1_Passives [InxSignalClass('xSignals_PHY1_Passives_MatchLengthsClass')] p9: tolerance=7.87 checknetsindiffpair=FALSE checkdiffpairvsdiffpair=TRUE checkxsignals=TRUE checkothers=TRUE
MatchedLengths MatchLengths_xSignals_PHY1_1 [InxSignalClass('xSignals_PHY1_MatchLengthsClass')] p10: tolerance=7.87 checknetsindiffpair=FALSE checkdiffpairvsdiffpair=TRUE checkxsignals=TRUE checkothers=TRUE
MatchedLengths MatchLengths_xSignals_PHY2 [InxSignalClass('xSignals_PHY2')] p11: tolerance=7.87 checknetsindiffpair=FALSE checkdiffpairvsdiffpair=TRUE checkxsignals=TRUE checkothers=TRUE
MatchedLengths MatchLengths_xSignals_RGMII_PHY2 [InxSignalClass('xSignals_RGMII_PHY2')] p12: tolerance=7.87 checknetsindiffpair=FALSE checkdiffpairvsdiffpair=TRUE checkxsignals=TRUE checkothers=TRUE
MatchedLengths MatchLengths_xSignals_RGMII_PHY1 [InxSignalClass('xSignals_RGMII_PHY1')] p13: tolerance=7.87 checknetsindiffpair=FALSE checkdiffpairvsdiffpair=TRUE checkxsignals=TRUE checkothers=TRUE
MatchedLengths MatchLengths_xSignals_PHY1 [InxSignalClass('xSignals_PHY1')] p14: tolerance=7.87 checknetsindiffpair=FALSE checkdiffpairvsdiffpair=TRUE checkxsignals=TRUE checkothers=TRUE
MinimumAnnularRing MinimumAnnularRing_ThermalPadVias [IsVia and InAnyComponent] p1: minimumring=3.35
MinimumAnnularRing [All] p2: minimumring=4.88
MinimumSolderMaskSliver MinimumSolderMaskSliver_Logo [InComponentClass('Logo') vs InComponentClass('Logo')] p1: minsoldermaskwidth=0.7
MinimumSolderMaskSliver [All] p2: minsoldermaskwidth=2.72
ParallelSegment [InNetClass('CLKs')] p1: limit=10000 gap=14.76
PlaneConnect [All] p1: planeconnectstyle=Relief reliefexpansion=10 reliefentries=4 reliefconductorwidth=10 reliefairgap=10
PolygonConnect PolygonConnect_Vias [IsVia] p1: connectstyle=Direct reliefconductorwidth=10 reliefentries=4 polygonreliefangle="90 Angle" airgapwidth=10
PolygonConnect PolygonConnect_DirectConnect [(OnTopLayer or OnBottomLayer) and ((ObjectKind = 'Poly') And (Name = 'DirectConnect')) vs IsSMTPin] p2: connectstyle=Direct reliefconductorwidth=10 reliefentries=4 polygonreliefangle="90 Angle" airgapwidth=10
PolygonConnect "PolygonConnect_under BGA" [OnBottomLayer and WithinRoom('RuleArea_BGA 0.8mm')] p3: connectstyle=Relief reliefconductorwidth=5.91 reliefentries=4 polygonreliefangle="90 Angle" airgapwidth=10
PolygonConnect [All] p4: connectstyle=Relief reliefconductorwidth=9.84 reliefentries=4 polygonreliefangle="90 Angle" airgapwidth=4
RoomDefinition "AMIC110 ICE EVM_Power" [InComponentClass('AMIC110 ICE EVM_Power')] p1 off: confinementstyle=ConfineIn formatcopy=TRUE lockcomponents=FALSE outline 2318.9,346.46 627.95,346.46 627.95,935.04 517.72,1045.28 517.72,1854.33 1043.31,1854.33 1043.31,1816.93 2318.9,1816.93
RoomDefinition "AMIC110 ICE EVM_SC_0" [InComponentClass('AMIC110 ICE EVM_SC_0')] p2 off: confinementstyle=ConfineIn formatcopy=TRUE lockcomponents=FALSE outline 633.86,370.08 633.86,1681.1 1653.54,1681.1 1653.54,1401.57 1751.97,1401.57 1751.97,1145.67 1649.61,1145.67 1649.61,960.63 1405.51,960.63 1405.51,370.08
RoomDefinition "AMIC110 ICE EVM_PHY" [InComponentClass('AMIC110 ICE EVM_PHY')] p3 off: confinementstyle=ConfineIn formatcopy=TRUE lockcomponents=FALSE outline 714.76,877.95 714.76,1591.93 3.74,1591.93 3.74,877.95
RoutingVias ThermalPadVias [IsVia and InAnyComponent] p1: holewidth=7.87 width=19.68 viastyle="Through Hole" minholewidth=7.87 minwidth=15 maxholewidth=12.99 maxwidth=23.62
RoutingVias [All] p2: holewidth=7.87 width=19.68 viastyle="Through Hole" minholewidth=7.87 minwidth=17.72 maxholewidth=39.37 maxwidth=62.99
SilkToSilkClearance SilkToSilkClearance_Pb-FreeLogo [(HasFootprint('Pb-Free_Overlay_Medium') OR HasFootprint('Pb-Free_Overlay_Small')) or ((ObjectKind = 'Region') And (Layer = 'TopOverlay')) or ((ObjectKind = 'Text') And (Layer = 'TopOverlay') And (StringText = 'GCD')) vs (HasFootprint('Pb-Free_Overlay_Medium') OR HasFootprint('Pb-Free_Overlay_Small')) or ((ObjectKind = 'Region') And (Layer = 'TopOverlay')) or ((ObjectKind = 'Text') And (Layer = 'TopOverlay') And (StringText = 'GCD'))] p1: silktosilkclearance=0
SilkToSilkClearance [All] p2: silktosilkclearance=3.94
SilkToSolderMaskClearance "Silk to Solder Mask Opening" [ALL and not isvia vs All and not isvia] p1: minsilkscreentomaskgap=0.98 clearancetoexposedcopper=TRUE
SolderMaskExpansion "SolderMaskExpansion_Vias (0.45/0.2)" [(ObjectKind = 'Via') And (ViaDiameter = AsMM(0.45)) And (HoleDiameter = AsMM(0.2))] p1: expansion=-4.33
SolderMaskExpansion "SolderMaskExpansion_Vias (0.5/0.2)" [(ObjectKind = 'Via') And (ViaDiameter = AsMM(0.5)) And (HoleDiameter = AsMM(0.2))] p2: expansion=-4.92
SolderMaskExpansion "SolderMaskExpansion_Vias (0.7/0.3)" [(ObjectKind = 'Via') And (ViaDiameter = AsMM(0.7)) And (HoleDiameter = AsMM(0.3))] p3: expansion=-7.28
SolderMaskExpansion "SolderMaskExpansion_Vias (28/10)" [(ObjectKind = 'Via') And (ViaDiameter = AsMils(28)) And (HoleDiameter = AsMils(10))] p4: expansion=-7
SolderMaskExpansion [All] p5: expansion=1.97
Width Width_Zdiff=100R [InNetClass('Zdiff=100R')] p1: maxlimit=11.81 minlimit=3.98 preferedwidth=3.98 toplayer_maxwidth=5.91 midlayer1_maxwidth=5.91 midlayer2_maxwidth=5.91 midlayer3_maxwidth=5.91 midlayer4_maxwidth=5.91 midlayer5_maxwidth=5.91 midlayer6_maxwidth=5.91 minimp=50.000000 maximp=50.000000 favimp=50.000000
Width Width_Zdiff=90R [InNetClass('Zdiff=90R')] p2 off: maxlimit=5.91 minlimit=5.12 preferedwidth=5.12 toplayer_minwidth=0 minimp=50.000000 maximp=50.000000 favimp=50.000000
Width Width_Z0=50R [InNetClass('Z0=50R') or InxSignalClass('xSignals_PHY1') or InxSignalClass('xSignals_PHY2')] p3: maxlimit=4.92 minlimit=4.68 preferedwidth=4.68 toplayer_minwidth=4.92 toplayer_prefwidth=4.92 bottomlayer_minwidth=4.92 bottomlayer_prefwidth=4.92 minimp=50.000000 maximp=50.000000 favimp=50.000000
Width [All and not InNetClass('Zdiff=100R')] p4: maxlimit=100 minlimit=4.68 preferedwidth=10 minimp=50.000000 maximp=50.000000 favimp=50.000000 checkconnectedcopper=TRUE
14 further rules are at their usual default settings.

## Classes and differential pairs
component class RoomDefinition_DDR3: C5 C6 C7 C8 C9 C10 C11 C12 C13 C14 C15 C16 C17 C18 C19 C20 C21 C22 C31 C33 C52 C136 C137 C141 C145 C149 C153 C157 C158 C161 C169 R30 R31 R32 R35 R66 R136 R140 R141 R145 R146 R150 R152 R153 R154 R155 R157 R159 R160 R161 R162 R163 R168 U1 Y3
net class PWR: 1V1 1V5 1V8_1 1V8_2 3V3 GND VIN5V
component class "AMIC110 ICE EVM_SC_0": C168 C169 C170 C171 C183 R53 R138 R139 R140 R141 R142 R143 R144 R145 R146 R147 R148 R149 R150 R151 R152 R153 R154 R155 R156 R157 R158 R159 R160 R161 R163 R164 R165 R166 R167 R169 R179 R183 R207 R208 R209 R210 R211 R212 R228 R229 R230 R231 R232 R233 R234 R237 U11 Y3
component class "AMIC110 ICE EVM_PS": C91 C92 C93 C94 C95 C96 C97 C98 C99 C100 C101 C102 C103 C104 C105 C106 C107 C108 C109 C110 C111 C112 C113 C114 C115 C116 C117 C118 C119 C120 C121 C122 C123 C124 C125 C126 C127 C128 C129 C130 C131 C132 C133 C134 C135 C136 C137 C138 C139 C140 C141 C142 C143 C144 C145 C146 C147 C148 C149 C150 C151 C152 C153 C154 C155 C156 C157 C158 C159 C160 C161 C162 C163 C164 C165 C166 C167 C182 R182
component class "AMIC110 ICE EVM_BootConfig": C88 C89 C90 R103 R104 R105 R106 R107 R108 R109 R110 R111 R112 R113 R114 R115 R116 R117 R118 R119 R120 R121 R122 R123 R124 R125 R126 R127 R128 R129 R130 R131 R132 R133 R134 R135 R136 R137 R191 R192 R193 R194 R195 R196 R197 R198 R199 R200 R201 R202 R203 R204 R205 R206 U8 U9 U10
component class "AMIC110 ICE EVM_Power": C70 C71 C72 C73 C74 C75 C76 C77 C78 C79 C80 C81 C82 C83 C84 C85 C86 C87 C177 C178 C179 C180 C181 D11 D12 D13 D14 D15 J8 L1 L2 L3 L4 R77 R78 R79 R80 R81 R82 R83 R84 R85 R86 R87 R88 R89 R90 R91 R92 R93 R94 R95 R96 R97 R98 R99 R100 R101 R102 R178 TP8 TP9 TP10 U7
component class "AMIC110 ICE EVM_PHY": C24 C25 C26 C27 C28 C29 C30 C31 C32 C33 C34 C35 C36 C37 C38 C39 C40 C41 C42 C43 C44 C45 C46 C47 C48 C49 C50 C51 C52 C53 C54 C55 C56 C57 C58 C59 C60 C61 C62 C63 C64 C65 C66 C67 C68 C69 C184 C186 J6 J7 R41 R42 R43 R44 R45 R46 R47 R48 R49 R50 R51 R52 R54 R56 R57 R58 R59 R60 R61 R62 R63 R64 R65 R66 R67 R68 R69 R70 R71 R72 R73 R74 R75 R220 R221 R222 R223 R224 R225 R226 R227 T1 T2 U3 U4 U5 U6 Y1 Y2
component class "AMIC110 ICE EVM_Led": D2 D3 D4 D5 D6 D7 D8 D9 D10 D16 D17 D18 D19 D20 Q1 Q2 Q3 Q4 Q5 Q6 R14 R15 R16 R17 R18 R19 R20 R21 R22 R23 R24 R25 R26 R27 R28 R29 R30 R31 R32 R33 R188 R189 R235 R236
component class "AMIC110 ICE EVM_Interfaces": C1 C2 C3 C172 C173 C174 C175 J1 J2 J3 J4 J5 J9 R1 R2 R3 R4 R5 R6 R7 R8 R9 R10 R11 R12 R13 R55 R76 R162 R168 R170 R171 R172 R173 R174 R175 R176 R177 R180 R181 R184 R185 R186 R187 R213 R214 R215 R216 S1 U12 U13 U14 U15
component class Header: J1 J3 J9
component class "Mounting Holes": H1 H2
component class "AMIC110 ICE EVM_HW": FID1 FID2 FID3 FID4 FID5 FID6 H1 H2 LBL1 Logo2 Logo3 Logo4 Logo5 ZZ1 ZZ2 ZZ3 ZZ4
component class FiducialMark: FID1 FID2 FID3 FID4 FID5 FID6
component class AssemblyNote: ZZ1 ZZ2 ZZ3 ZZ4
component class Label: LBL1
net class PHY1_RGMII_TX: NetR142_2 NetR154_1 NetR156_1 NetR157_1 NetR158_1 NetR159_1 PHY1_TXCLK PHY1_TXD0 PHY1_TXD1 PHY1_TXD2 PHY1_TXD3 PHY1_TXEN
net class PHY1_RGMII_RX: PHY1_RXCLK PHY1_RXD0 PHY1_RXD1 PHY1_RXD2 PHY1_RXD3 PHY1_RXDV PHY1_RXER
net class PHY2_RGMII_TX: NetR146_1 NetR147_1 NetR160_1 NetR164_1 NetR167_1 PHY2_TXCLK PHY2_TXD0 PHY2_TXD1 PHY2_TXD2 PHY2_TXD3 PHY2_TXEN
net class PHY2_RGMII_RX: PHY2_RXCLK PHY2_RXD0 PHY2_RXD1 PHY2_RXD2 PHY2_RXD3 PHY2_RXDV PHY2_RXER
component class "AMIC110 ICE EVM_Memory": C5 C6 C7 C8 C9 C10 C11 C12 C13 C14 C15 C16 C17 C18 C19 C20 C21 C22 C23 C176 R34 R35 R36 R37 R38 R39 R40 R190 R217 R218 R219 R238 R239 R240 U1 U2 U16
net class Z0=50R: DDR_A0 DDR_A1 DDR_A2 DDR_A3 DDR_A4 DDR_A5 DDR_A6 DDR_A7 DDR_A8 DDR_A9 DDR_A10 DDR_A11 DDR_A12 DDR_A13 DDR_A14 DDR_A15 DDR_BA0 DDR_BA1 DDR_BA2 DDR_CASN DDR_CSN DDR_D0 DDR_D1 DDR_D2 DDR_D3 DDR_D4 DDR_D5 DDR_D6 DDR_D7 DDR_D8 DDR_D9 DDR_D10 DDR_D11 DDR_D12 DDR_D13 DDR_D14 DDR_D15 DDR_DQM0 DDR_DQM1 DDR_ODT DDR_RASN DDR_RESETN DDR_WEN ECAT_SYNC0 ECAT_SYNC1 JTAG_EMU0 JTAG_EMU1 JTAG_TCK JTAG_TDI JTAG_TDO JTAG_TMS JTAG_TRSTN PHY1_CLKOUT PHY1_COL PHY1_CRS PHY1_RXCLK PHY1_RXD0 PHY1_RXD1 PHY1_RXD2 PHY1_RXD3 PHY1_RXDV PHY1_RXER PHY1_TXCLK PHY1_TXD0 PHY1_TXD1 PHY1_TXD2 PHY1_TXD3 PHY1_TXEN PHY2_COL PHY2_CRS PHY2_RXCLK PHY2_RXD0 PHY2_RXD1 PHY2_RXD2 PHY2_RXD3 PHY2_RXDV PHY2_RXER PHY2_TXCLK PHY2_TXD0 PHY2_TXD1 PHY2_TXD2 PHY2_TXD3 PHY2_TXEN PHY2_WOL PHY_MDC PHY_MDIO SPI0_CS0N SPI0_D0 SPI0_D1 SPI0_SCLK SPI_D0 SPI_D1_MCASP1_AFSX_MFSRB SPICLK SPICS SYS_BOOT6_GPIO SYS_BOOT7_GPIO SYS_RESETN TCK TDIS
net class CLKs: DDR_CKE PHY1_CLKOUT PHY1_RXCLK PHY1_TXCLK PHY2_RXCLK PHY2_TXCLK RTCK SPI0_SCLK SPICLK TCK
net class Zdiff=100R: DDR_CK DDR_CKN DDR_DQS0 DDR_DQS1 DDR_DQSN0 DDR_DQSN1 PHY1_RD_N PHY1_RD_P PHY1_RJ_RD_N PHY1_RJ_RD_P PHY1_RJ_TD_N PHY1_RJ_TD_P PHY1_TD_N PHY1_TD_P PHY2_RD_N PHY2_RD_P PHY2_RJ_RD_N PHY2_RJ_RD_P PHY2_RJ_TD_N PHY2_RJ_TD_P PHY2_TD_N PHY2_TD_P
differential pair class Zdiff=100R: PHY1_RD PHY1_RJ_RD PHY1_RJ_TD PHY1_TD PHY2_RD PHY2_RJ_RD PHY2_RJ_TD PHY2_TD
component class "Room Definition_PWR": C70 C71 C72 C73 C74 C75 C80 C81 C84 C103 C107 C108 C111 L1 L2 L3 R46 R55 R57 R67 R80 R81 R85 R86 R89 R90 R92 R93 R94 R96 R97 R98 R99 R100 R102 U7
net class SPI: SPI_D0 SPI_D1_MCASP1_AFSX_MFSRB SPICLK SPICS
net class DDR3: DDR_A0 DDR_A1 DDR_A2 DDR_A3 DDR_A4 DDR_A5 DDR_A6 DDR_A7 DDR_A8 DDR_A9 DDR_A10 DDR_A11 DDR_A12 DDR_A13 DDR_A14 DDR_A15 DDR_BA0 DDR_BA1 DDR_BA2 DDR_CASN DDR_CK DDR_CKE DDR_CKN DDR_CSN DDR_D0 DDR_D1 DDR_D2 DDR_D3 DDR_D4 DDR_D5 DDR_D6 DDR_D7 DDR_D8 DDR_D9 DDR_D10 DDR_D11 DDR_D12 DDR_D13 DDR_D14 DDR_D15 DDR_DQM0 DDR_DQM1 DDR_DQS0 DDR_DQS1 DDR_DQSN0 DDR_DQSN1 DDR_ODT DDR_RASN DDR_RESETN DDR_VREF DDR_WEN
differential pair PHY2_RJ_TD: +PHY2_RJ_TD_P -PHY2_RJ_TD_N
differential pair PHY2_RJ_RD: +PHY2_RJ_RD_P -PHY2_RJ_RD_N
differential pair PHY1_RJ_TD: +PHY1_RJ_TD_P -PHY1_RJ_TD_N
differential pair PHY1_RJ_RD: +PHY1_RJ_RD_P -PHY1_RJ_RD_N
differential pair PHY2_TD: +PHY2_TD_P -PHY2_TD_N
differential pair PHY2_RD: +PHY2_RD_P -PHY2_RD_N
differential pair PHY1_TD: +PHY1_TD_P -PHY1_TD_N
differential pair PHY1_RD: +PHY1_RD_P -PHY1_RD_N

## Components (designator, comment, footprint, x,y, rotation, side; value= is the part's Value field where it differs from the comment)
C1 "GRM033R71A103KA01D" 0201 610.24,1819.88 r0 bottom value=0.01uF
C2 "GRM155R71A104KA01D" 0402 523.62,2027.56 r0 bottom value=0.1uF
C3 "GRM155R70J104KA01D" 0402 468.5,437.01 r270 bottom value=0.1uF
C5 "GRM155R71C102KA01D" 0402 1002.17,650.4 r270 bottom value=1000pF
C6 "GRM155R70J104KA01D" 0402 907.67,650.4 r90 bottom value=0.1uF
C7 "885012207026" 0805_HV 1330.42,475.4 r270 bottom value=10uF
C8 "885012207026" 0805_HV 705.42,475.4 r270 bottom value=10uF
C9 "885012205037" 0402 1002.17,450.4 r270 bottom value=0.1uF
C10 "885012205037" 0402 860.42,450.4 r270 bottom value=0.1uF
C11 "885012205037" 0402 797.42,450.4 r270 bottom value=0.1uF
C12 "885012205037" 0402 1269.92,850.4 r90 bottom value=0.1uF
C13 "885012205037" 0402 1206.92,850.4 r90 bottom value=0.1uF
C14 "885012205037" 0402 1112.42,850.4 r90 bottom value=0.1uF
C15 "885012205037" 0402 1049.42,850.4 r90 bottom value=0.1uF
C16 "885012205037" 0402 954.92,850.4 r90 bottom value=0.1uF
C17 "885012205037" 0402 860.42,850.4 r90 bottom value=0.1uF
C18 "885012205037" 0402 797.42,850.4 r90 bottom value=0.1uF
C19 "885012205037" 0402 1269.92,450.4 r270 bottom value=0.1uF
C20 "885012205037" 0402 1206.92,450.4 r270 bottom value=0.1uF
C21 "885012205037" 0402 1143.92,450.4 r270 bottom value=0.1uF
C22 "885012205037" 0402 1049.42,450.4 r270 bottom value=0.1uF
C23 "GRM155R70J104KA01D" 0402 498.03,1669.29 r0 bottom value=0.1uF
C24 "GRM155R70J105MA12D" 0402L 2161.42,915.35 r0 bottom value=1uF
C25 "GRM155R70J105MA12D" 0402L 2161.42,744.09 r180 bottom value=1uF
C26 "885012205037" 0402L 2161.42,915.35 r0 top value=0.1uF
C27 "885012205037" 0402L 2161.42,738.19 r180 top value=0.1uF
C28 "GRM0335C1H4R7CA01D" 0201 2273.62,742.13 r180 bottom value=4.7pF
C29 "GRM0335C1H4R7CA01D" 0201 2273.62,714.57 r180 bottom value=4.7pF
C30 "GRM0335C1H4R7CA01D" 0201 2273.62,683.07 r180 bottom value=4.7pF
C31 "GRM0335C1H4R7CA01D" 0201 2273.62,655.51 r180 bottom value=4.7pF
C32 "885012207026" 0805_HV 2039.37,1153.54 r0 top value=10uF
C33 "885012205031" 0402 2013.78,1094.49 r0 top value=0.01uF
C34 "885012205044" 0402 2013.78,1055.12 r0 top value=1000pF
C35 "CC0402KRX7R9BB101" 0402 2013.78,1015.75 r0 top value=100pF
C36 "885012207026" 0805_HV 2192.91,1153.54 r0 top value=10uF
C37 "885012205031" 0402 2167.32,1066.93 r0 top value=0.01uF
C38 "885012205044" 0402 2167.32,1015.75 r0 top value=1000pF
C39 "CC0402KRX7R9BB101" 0402 2167.32,964.57 r0 top value=100pF
C40 "GRM155R70J105MA12D" 0402 2427.47,862.4 r180 bottom value=1uF
C41 "885012205037" 0402 2427.47,817.12 r180 bottom value=0.1uF
C42 "885012205037" 0402 2426.03,580.38 r180 bottom value=0.1uF
C43 "GRM155R70J105MA12D" 0402 2426.03,535.11 r180 bottom value=1uF
C44 "C1812C103KDRACTU" 1812_180 2496.06,698.82 r180 bottom value=0.01uF
C45 "GRM1555C1H200JA01D" 0402 1753.94,1173.23 r270 top value=20pF
C46 "GRM1555C1H200JA01D" 0402 1753.94,1070.87 r90 top value=20pF
C47 "GRM155R70J105MA12D" 0402L 2161.42,1478.35 r0 bottom value=1uF
C48 "GRM155R70J105MA12D" 0402L 2162.4,1301.18 r180 bottom value=1uF
C49 "885012205037" 0402L 2161.42,1478.35 r0 top value=0.1uF
C50 "885012205037" 0402L 2161.42,1301.18 r180 top value=0.1uF
C51 "GRM0335C1H4R7CA01D" 0201 2273.62,1549.21 r180 bottom value=4.7pF
C52 "GRM0335C1H4R7CA01D" 0201 2273.62,1521.65 r180 bottom value=4.7pF
C53 "GRM0335C1H4R7CA01D" 0201 2273.62,1490.16 r180 bottom value=4.7pF
C54 "GRM0335C1H4R7CA01D" 0201 2273.62,1462.6 r180 bottom value=4.7pF
C55 "885012207026" 0805_HV 2021.65,1716.54 r0 top value=10uF
C56 "885012205031" 0402 1996.06,1657.48 r0 top value=0.01uF
C57 "885012205044" 0402 1996.06,1618.11 r0 top value=1000pF
C58 "CC0402KRX7R9BB101" 0402 1996.06,1578.74 r0 top value=100pF
C59 "GRM155R70J105MA12D" 0402 2426.34,1669.3 r180 bottom value=1uF
C60 "885012205037" 0402 2426.34,1624.02 r180 bottom value=0.1uF
C61 "885012205037" 0402 2427.44,1387.67 r180 bottom value=0.1uF
C62 "GRM155R70J105MA12D" 0402 2427.44,1342.4 r180 bottom value=1uF
C63 "885012207026" 0805_HV 2179.13,1716.54 r0 top value=10uF
C64 "885012205031" 0402 2153.54,1629.92 r0 top value=0.01uF
C65 "885012205044" 0402 2153.54,1578.74 r0 top value=1000pF
C66 "CC0402KRX7R9BB101" 0402 2153.54,1527.56 r0 top value=100pF
C67 "C1812C103KDRACTU" 1812_180 2496.06,1505.91 r180 bottom value=0.01uF
C68 "GRM1555C1H200JA01D" 0402 1736.22,1736.22 r270 top value=20pF
C69 "GRM1555C1H200JA01D" 0402 1736.22,1633.86 r270 top value=20pF
C70 "C1608X5R1E106M080AC" 0603 496.06,1419.29 r270 top value=10uF
C71 "C1608X5R1E106M080AC" 0603 442.91,1417.32 r270 top value=10uF
C72 "GRM155R70J105MA12D" 0402 354.33,1120.08 r180 top value=1uF
C73 "C1608X5R1E106M080AC" 0603 442.91,1301.18 r90 top value=10uF
C74 "C1608X5R1E106M080AC" 0603 131.89,1100.39 r0 top value=10uF
C75 "C1608X5R1E106M080AC" 0603 131.89,1153.54 r0 top value=10uF
C76 "GRM155R70J105MA12D" 0402 175.2,832.68 r180 top value=1uF
C77 "GRM155R70J105MA12D" 0402 379.92,702.76 r180 top value=1uF
C78 "C1608X5R1E106M080AC" 0603 250,1100.39 r180 top value=10uF
C79 "GRM155R70J105MA12D" 0402 78.74,789.37 r0 top value=1uF
C80 "C1608X5R1E106M080AC" 0603 496.06,1120.08 r90 top value=10uF
C81 "C1608X5R1E106M080AC" 0603 442.91,1120.08 r90 top value=10uF
C82 "C1608X5R1E106M080AC" 0603 496.06,1238.19 r270 top value=10uF
C83 "GRM155R70J105MA12D" 0402 78.74,702.76 r180 top value=1uF
C84 "GRM188R71A225KE15D" 0603 110.24,1456.69 r90 top value=2.2uF
C85 "GRM155R70J105MA12D" 0402 78.74,616.14 r180 top value=1uF
C86 "GRM155R70J105MA12D" 0402 187.01,1446.85 r90 top value=1uF
C87 "GRM188R71A225KE15D" 0603 259.84,1456.69 r90 top value=2.2uF
C88 "885012205037" 0402 2094.49,608.27 r270 bottom value=0.1uF
C89 "885012205037" 0402L 1679.13,700.79 r0 bottom value=0.1uF
C90 "885012205037" 0402L 1622.05,836.61 r0 top value=0.1uF
C91 "GRM033R71A103KA01D" 0201L 1379.92,1261.81 r0 bottom value=0.01uF
C92 "GRM033R71A103KA01D" 0201L 1379.92,1287.4 r0 bottom value=0.01uF
C93 "C1608X5R1E106M080AC" 0603L 1500,1226.38 r0 bottom value=10uF
C94 "GRM033R71A103KA01D" 0201L 1340.55,1399.61 r0 bottom value=0.01uF
C95 "GRM033R71A103KA01D" 0201L 1340.55,1364.17 r0 bottom value=0.01uF
C96 "C1608X5R1E106M080AC" 0603L 1500,1279.53 r180 bottom value=10uF
C97 "GRM033R71A103KA01D" 0201L 1340.55,1427.17 r180 bottom value=0.01uF
C98 "GRM033R71A103KA01D" 0201L 1340.55,1462.6 r180 bottom value=0.01uF
C99 "C1608X5R1E106M080AC" 0603L 1500,1332.68 r0 bottom value=10uF
C100 "GRM033R71A103KA01D" 0201L 1192.91,1507.87 r180 bottom value=0.01uF
C101 "GRM033R71A103KA01D" 0201L 1129.92,1507.87 r0 bottom value=0.01uF
C102 "C1608X5R1E106M080AC" 0603L 1192.91,1625.98 r270 bottom value=10uF
C103 "GRM033R71A103KA01D" 0201L 1253.94,1472.44 r0 bottom value=0.01uF
C104 "GRM033R71A103KA01D" 0201L 1253.94,1498.03 r0 bottom value=0.01uF
C105 "C1608X5R1E106M080AC" 0603L 1287.4,1625.98 r90 bottom value=10uF
C106 "GRM033R71A103KA01D" 0201L 1076.77,1362.2 r180 bottom value=0.01uF
C107 "GRM033R71A103KA01D" 0201L 1003.94,1393.7 r0 bottom value=0.01uF
C108 "GRM033R71A103KA01D" 0201L 1016.73,1476.38 r270 bottom value=0.01uF
C109 "GRM033R71A103KA01D" 0201L 991.14,1476.38 r270 bottom value=0.01uF
C110 "GRM033R71A103KA01D" 0201L 1083.66,1539.37 r270 bottom value=0.01uF
C111 "GRM033R71A103KA01D" 0201L 1058.07,1539.37 r270 bottom value=0.01uF
C112 "GRM033R71A103KA01D" 0201L 1267.72,1202.76 r270 bottom value=0.01uF
C113 "GRM033R71A103KA01D" 0201L 1318.9,1224.41 r0 bottom value=0.01uF
C114 "GRM033R71A103KA01D" 0201L 1318.9,1192.91 r0 bottom value=0.01uF
C115 "C1608X5R1E106M080AC" 0603L 1074.8,1625.98 r270 bottom value=10uF
C116 "CL03A104KP3NNNC" 0201L 1053.15,1214.57 r270 bottom value=0.1uF
C117 "CL03A104KP3NNNC" 0201L 1192.91,1448.82 r180 bottom value=0.1uF
C118 "CL03A104KP3NNNC" 0201L 1379.92,1318.9 r0 bottom value=0.1uF
C119 "GRM033R71A103KA01D" 0201L 1076.77,1336.61 r0 bottom value=0.01uF
C120 "GRM033R71A103KA01D" 0201L 1032.48,1539.37 r90 bottom value=0.01uF
C121 "GRM033R71A103KA01D" 0201L 1303.15,1275.59 r0 bottom value=0.01uF
C122 "GRM033R71A103KA01D" 0201L 1340.55,1490.16 r180 bottom value=0.01uF
C123 "C1608X5R1E106M080AC" 0603L 797.24,1240.16 r180 bottom value=10uF
C124 "GRM033R71A103KA01D" 0201L 1110.24,1551.18 r90 bottom value=0.01uF
C125 "GRM033R71A103KA01D" 0201L 1025.59,1364.17 r180 bottom value=0.01uF
C126 "GRM033R71A103KA01D" 0201L 1338.58,1582.68 r90 bottom value=0.01uF
C127 "GRM033R71A103KA01D" 0201L 1364.17,1582.68 r90 bottom value=0.01uF
C128 "GRM033R71A103KA01D" 0201L 1352.36,1539.37 r180 bottom value=0.01uF
C129 "GRM033R71A103KA01D" 0201L 1289.37,1539.37 r180 bottom value=0.01uF
C130 "GRM033R71A103KA01D" 0201L 1025.59,1338.58 r180 bottom value=0.01uF
C131 "GRM155R70J105MA12D" 0402L 807.09,1336.61 r180 bottom value=1uF
C132 "GRM155R70J105MA12D" 0402L 807.09,1452.76 r180 bottom value=1uF
C133 "GRM155R70J105MA12D" 0402L 807.09,1413.39 r180 bottom value=1uF
C134 "GRM033R71A103KA01D" 0201L 1057.09,1287.4 r90 bottom value=0.01uF
C135 "GRM033R71A103KA01D" 0201L 1381.89,1350.39 r270 bottom value=0.01uF
C136 "C1608X5R1E106M080AC" 0603L 792.92,1025.4 r180 bottom value=10uF
C137 "C1608X5R1E106M080AC" 0603L 799.21,1100.39 r180 top value=10uF
C138 "CL03A104KP3NNNC" 0201L 1204.72,1202.76 r90 bottom value=0.1uF
C139 "CL03A104KP3NNNC" 0201L 1179.13,1202.76 r90 bottom value=0.1uF
C140 "CL03A104KP3NNNC" 0201L 1143.7,1202.76 r90 bottom value=0.1uF
C141 "CL03A104KP3NNNC" 0201L 1118.11,1202.76 r90 bottom value=0.1uF
C142 "CL03A104KP3NNNC" 0201L 817.92,1100.4 r180 bottom value=0.1uF
C143 "CL03A104KP3NNNC" 0201L 680.42,1037.9 r0 bottom value=0.1uF
C144 "CL03A104KP3NNNC" 0201L 680.42,1000.4 r0 bottom value=0.1uF
C145 "GRM033R71A103KA01D" 0201L 984.25,1224.41 r270 bottom value=0.01uF
C146 "GRM033R71A103KA01D" 0201L 1417.32,1397.64 r0 bottom value=0.01uF
C147 "C1608X5R1E106M080AC" 0603L 797.24,1293.31 r180 bottom value=10uF
C148 "C1608X5R1E106M080AC" 0603L 1192.91,1326.77 r90 bottom value=10uF
C149 "GRM033R71A103KA01D" 0201L 1078.74,1214.57 r270 bottom value=0.01uF
C150 "GRM033R71A103KA01D" 0201L 1082.68,1287.4 r90 bottom value=0.01uF
C151 "GRM033R71A103KA01D" 0201L 1108.27,1287.4 r90 bottom value=0.01uF
C152 "GRM033R71A103KA01D" 0201L 1129.92,1350.39 r270 bottom value=0.01uF
C153 "GRM033R71A103KA01D" 0201L 1181.1,1403.54 r270 bottom value=0.01uF
C154 "GRM033R71A103KA01D" 0201L 1206.69,1403.54 r270 bottom value=0.01uF
C155 "GRM033R71A103KA01D" 0201L 1244.09,1364.17 r180 bottom value=0.01uF
C156 "GRM033R71A103KA01D" 0201L 1244.09,1336.61 r180 bottom value=0.01uF
C157 "GRM033R71A103KA01D" 0201L 1307.09,1480.31 r90 bottom value=0.01uF
C158 "GRM033R71A103KA01D" 0201L 1307.09,1437.01 r270 bottom value=0.01uF
C159 "GRM033R71A103KA01D" 0201L 1303.15,1336.61 r180 bottom value=0.01uF
C160 "GRM033R71A103KA01D" 0201L 1214.57,1267.72 r180 bottom value=0.01uF
C161 "GRM033R71A103KA01D" 0201L 1214.57,1242.13 r180 bottom value=0.01uF
C162 "C1608X5R1E106M080AC" 0603L 799.21,1295.28 r180 top value=10uF
C163 "GRM033R71A103KA01D" 0201L 1098.43,1413.39 r90 bottom value=0.01uF
C164 "GRM033R71A103KA01D" 0201L 1066.93,1413.39 r270 bottom value=0.01uF
C165 "GRM033R71A103KA01D" 0201L 1068.9,1476.38 r180 bottom value=0.01uF
C166 "GRM033R71A103KA01D" 0201L 1129.92,1476.38 r180 bottom value=0.01uF
C167 "GRM033R71A103KA01D" 0201L 1192.91,1476.38 r0 bottom value=0.01uF
C168 "GRM1555C1H200JA01D" 0402 1696.85,1220.47 r90 top value=20pF
C169 "GRM033R71A103KA01D" 0201L 877.95,1507.87 r90 bottom value=0.01uF
C170 "GRM1555C1H200JA01D" 0402 1696.85,1322.83 r270 top value=20pF
C171 "GRM155R70J104KA01D" 0402 1112.42,950.4 r270 bottom value=0.1uF
C172 "GRM155R71A104KA01D" 0402 2188.98,1986.22 r180 top value=0.1uF
C173 "GRM155R71A104KA01D" 0402 2224.41,72.83 r270 top value=0.1uF
C174 "GRM155R71A104KA01D" 0402 903.54,214.57 r0 top value=0.1uF
C175 "GRM155R71A104KA01D" 0402 807.09,2120.08 r90 top value=0.1uF
C176 "GRM155R71A104KA01D" 0402 496.06,561.02 r0 bottom value=0.1uF
C177 "GRM188R61C475KAAJ" 0603 74.8,1736.22 r180 top value=4.7uF
C178 "GRM188R71C104KA01D" 0603 74.8,1677.17 r180 top value=0.1uF
C179 "GRM188R61A226ME15D" 0603 381.89,1649.61 r0 top value=22uF
C180 "GRM188R61A226ME15D" 0603 381.89,1706.69 r0 top value=22uF
C181 "GRM188R71C104KA01D" 0603 381.89,1763.78 r0 top value=0.1uF
C182 "GRM033R71A103KA01D" 0201L 974.41,1287.4 r180 bottom value=0.01uF
C183 "GRM033R71A103KA01D" 0201L 921.26,1301.18 r180 bottom value=0.01uF
C184 "202R18W102KV4E" 1206_190 2824.8,895.67 r90 bottom value=1000pF
C186 "202R18W102KV4E" 1206_190 2824.8,1309.06 r270 bottom value=1000pF
D2 "150060VS75000" WL-SMCW_GREEN 1484.25,460.63 r90 top value=Green
D3 "150060VS75000" WL-SMCW_GREEN 1570.87,460.63 r90 top value=Green
D4 "150060YS75000" WL-SMCW_YELLOW 1657.48,460.63 r90 top value=Yellow
D5 "VLMO1500-GS08" VLMx1500_Orange 1748.03,460.63 r270 top value=Orange
D6 "APTD1608LZGCK" APTD1608 1940.54,588.17 r180 top value=GREEN
D7 "150060RS75000" WL-SMCW_RED 1484.25,602.36 r90 top value=Red
D8 "150060VS75000" WL-SMCW_GREEN 1570.87,602.36 r90 top value=Green
D9 "150060YS75000" WL-SMCW_YELLOW 1657.48,602.36 r90 top value=Yellow
D10 "VLMO1500-GS08" VLMx1500_Orange 1748.03,602.36 r270 top value=Orange
D11 "MBR0540T1G" SOD-123 423.23,584.65 r180 top value=40V
D12 "MBR0540T1G" SOD-123 228.35,759.84 r180 top value=40V
D13 "MBR0540T1G" SOD-123 228.35,671.26 r180 top value=40V
D14 "MBR0540T1G" SOD-123 228.35,584.65 r180 top value=40V
D15 "150060VS75000" WL-SMCW_GREEN 78.74,1592.52 r0 top value=Green
D16 "APTD1608LSECK/J3-PF" APTD1608 1825.1,458.03 r90 top value=RED
D17 "APTD1608LZGCK" APTD1608 1945,411.41 r180 top value=GREEN
D18 "APTD1608LSYCK/J3-PF" APTD1608 1945,478.92 r180 top value=YELLOW
D19 "APTD1608LSECK/J3-PF" APTD1608 1841.47,630.1 r90 top value=RED
D20 "APTD1608LSYCK/J3-PF" APTD1608 1940.54,653.54 r180 top value=YELLOW
FID1 "Fiducial" Fiducial10-20 2685.04,301.18 r0 top
FID2 "Fiducial" Fiducial10-20 2685.39,1954.72 r0 top
FID3 "Fiducial" Fiducial10-20 395.67,301.97 r0 top
FID4 "Fiducial" Fiducial10-20 403.54,236.02 r180 bottom
FID5 "Fiducial" Fiducial10-20 2848.43,236.22 r180 bottom
FID6 "Fiducial" Fiducial10-20 2848.43,1946.85 r180 bottom
H1 "NY PMS 440 0025 PH" "NY PMS 440 0025 PH" 3326.77,137.8 r0 top locked
H2 "NY PMS 440 0025 PH" "NY PMS 440 0025 PH" 3326.77,2066.93 r0 top locked
J1 "FTR-110-51-S-D-06" Samtec_FTR-110-51-x-D-06 614.17,1925.2 r180 top
J2 "DF40HC(4.0)-60DS-0.4V(51)" Hirose_DF40HC-4_0-60DS-0_4V 157.48,295.28 r90 bottom
J3 "PEC06SAAN" Sullins_PEC06SAAN 2598.43,2096.46 r180 top
J4 "SSW-110-23-F-D" CONN_SSW-110-23-F-D 1515.75,1952.36 r0 bottom locked
J5 "SSW-110-23-F-D" CONN_SSW-110-23-F-D 1515.75,252.36 r0 bottom locked
J6 "1-406541-1" TEC_1-406541-1 3149.61,698.82 r90 top
J7 "1-406541-1" TEC_1-406541-1 3149.61,1505.91 r90 top
J8 "RAPC722X" CONN_RAPC722X 234.25,2401.57 r90 top
J9 "PEC01DAAN" Sullins_PxC01DAAN 2398.43,1946.85 r0 top
L1 "VLCF4020T-2R2N1R7" VLCF4020 614.17,1405.51 r90 top value=2.2uH
L2 "VLCF4020T-2R2N1R7" VLCF4020 145.67,982.28 r180 top value=2.2uH
L3 "VLCF4020T-3R3N1R5" VLCF4020 614.17,1133.86 r270 top value=3.3uH
L4 "XFL4020-152MEB" XFL4020 228.35,1706.69 r0 top value=1.5uH
LBL1 "Size: 0.65\" x 0.20 \"" LABEL_650X200 2582.68,124.02 r0 top
Logo2 "Pb-Free Symbol" Pb-Free_Overlay_Small 289.37,283.46 r0 top
Logo3 "FCC disclaimer" FCC_disclaimer 2318.9,2262.8 r90 bottom
Logo4 "ESD Susceptible" ESD_Overlay_Small 549.37,284.02 r0 top
Logo5 "ESD Susceptible" ESD_Overlay_Small 1931.1,1072.83 r180 bottom
Q1 "CSD13383F4" YJC0003A 2131.89,399.61 r180 top value=12V
Q2 "CSD13383F4" YJC0003A 2131.89,438.98 r180 top value=12V
Q3 "CSD13383F4" YJC0003A 2131.89,478.35 r180 top value=12V
Q4 "CSD13383F4" YJC0003A 2131.89,547.24 r180 top value=12V
Q5 "CSD13383F4" YJC0003A 2131.89,586.61 r180 top value=12V
Q6 "CSD13383F4" YJC0003A 2131.89,625.98 r180 top value=12V
R1 "CRCW04024K70JNED" 0402 592.52,1785.43 r180 bottom value=4.7k
R2 "CRCW04024K70JNED" 0402 639.76,1976.38 r180 bottom value=4.7k
R3 "CRCW04024K70JNED" 0402 592.52,1732.28 r180 bottom value=4.7k
R4 "CRCW04020000Z0ED" 0402 639.76,1870.08 r0 bottom value=0
R5 "CRCW04020000Z0ED" 0402 639.76,1923.23 r0 bottom value=0
R6 "CRCW04020000Z0ED" 0402 639.76,2082.68 r0 bottom value=0
R7 "CRCW04020000Z0ED" 0402 551.18,2109.25 r270 bottom value=0
R8 "CRCW04020000Z0ED" 0402 639.76,2135.83 r0 bottom value=0
R9 "CRCW0402100RJNED" 0402 639.76,2029.53 r0 bottom value=100
R10 "CRCW04021K00JNED" 0402 509.84,437.01 r270 bottom value=1.0k
R11 "CRCW04024K70JNED" 0402 527.56,1970.47 r0 bottom value=4.7k
R12 "CRCW04020000Z0ED" 0402L 1161.42,1814.96 r180 top value=0
R13 "CRCW04020000Z0ED" 0402L 1082.68,1814.96 r0 top value=0
R14 "CRCW040210K0JNED" 0402L 2208.66,399.61 r180 top value=10k
R15 "CRCW04021K60JNED" 0402L 2054.97,399.56 r0 top value=1.6k
R16 "CRCW04021K20JNED" 0402L 2053.15,438.98 r0 top value=1.2k
R17 "CRCW04021K60JNED" 0402L 2053.15,478.35 r0 top value=1.6k
R18 "CRCW040210K0JNED" 0402L 2208.66,438.98 r180 top value=10k
R19 "CRCW04021K50JNED" 0402L 1501.97,700.79 r90 top value=1.5k
R20 "CRCW04021K50JNED" 0402L 1539.37,700.79 r90 top value=1.5k
R21 "CRCW04021K50JNED" 0402L 1685.04,700.79 r90 top value=1.5k
R22 "CRCW04021K50JNED" 0402L 1757.87,700.79 r90 top value=1.5k
R23 "CRCW040210K0JNED" 0402L 2208.66,478.35 r180 top value=10k
R24 "CRCW04024K70JNED" 0402L 2208.66,547.24 r180 top value=4.7k
R25 "CRCW04021K60JNED" 0402L 2053.15,547.24 r0 top value=1.6k
R26 "CRCW04021K20JNED" 0402L 2053.15,586.61 r0 top value=1.2k
R27 "CRCW04021K60JNED" 0402L 2053.15,625.98 r0 top value=1.6k
R28 "CRCW04021K50JNED" 0402L 1464.57,700.79 r270 top value=1.5k
R29 "CRCW04021K50JNED" 0402L 1576.77,700.79 r90 top value=1.5k
R30 "CRCW04021K50JNED" 0402L 1649.61,700.79 r90 top value=1.5k
R31 "CRCW04021K50JNED" 0402L 1722.44,700.79 r90 top value=1.5k
R32 "CRCW040210K0JNED" 0402L 2208.66,586.61 r180 top value=10k
R33 "CRCW040210K0JNED" 0402L 2208.66,625.98 r180 top value=10k
R34 "CRCW040210K0FKED" 0402 1049.42,650.4 r90 bottom value=10.0k
R35 "CRCW040210K0FKED" 0402 954.92,650.4 r270 bottom value=10.0k
R36 "CRCW040210K0FKED" 0402 954.92,450.4 r90 bottom value=10.0k
R37 "CRCW04021K50FKED" 0402 797.42,650.4 r90 bottom value=1.50k
R38 "ERJ-2RKF2400X" 0402 907.67,450.4 r270 bottom value=240
R39 "CRCW040210K0FKED" 0402L 850.39,1568.9 r0 bottom value=10.0k
R40 "CRCW040210K0FKED" 0402 498.03,1732.28 r180 bottom value=10.0k
R41 "CRCW04020000Z0ED" 0402 2019.69,1220.47 r0 top value=0
R42 "CRCW040249R9FKED" 0402L 2161.42,879.92 r0 top value=49.9
R43 "CRCW040249R9FKED" 0402L 2161.42,844.49 r0 top value=49.9
R44 "CRCW040249R9FKED" 0402L 2161.42,809.06 r0 top value=49.9
R45 "CRCW040249R9FKED" 0402L 2161.42,773.62 r0 top value=49.9
R46 "CRCW04020000Z0ED" 0402 2173.23,1220.47 r0 top value=0
R47 "CRCW04024K87FKED" 0402 2041.34,925.2 r180 bottom value=4.87k
R48 "CRCW040210K0JNED" 0402l 2120.08,706.69 r180 bottom value=10k
R49 "HVC2010-1M0GT3" 2010 2495.89,948.36 r0 bottom value=1.00Meg
R50 "CRCW04020000Z0ED" 0402 1944.88,1070.87 r90 top value=0
R51 "CRCW04020000Z0ED" 0402L 1757.87,799.21 r90 top value=0
R52 "CRCW04020000Z0ED" 0402L 1793.31,799.21 r90 top value=0
R53 "CRCW04024K70JNED" 0402L 1820.87,927.17 r90 top value=4.7k
R54 "CRCW04020000Z0ED" 0402L 1757.87,885.83 r270 top value=0
R55 "CRCW040210K0JNED" 0402L 2092.52,2106.3 r180 top value=10k
R56 "CRCW04022K40JNED" 0402 2090.55,1043.31 r270 top value=2.4k
R57 "CRCW04020000Z0ED" 0402 2001.97,1783.46 r0 top value=0
R58 "CRCW040249R9FKED" 0402L 2161.42,1442.91 r0 top value=49.9
R59 "CRCW040249R9FKED" 0402L 2161.42,1407.48 r0 top value=49.9
R60 "CRCW040249R9FKED" 0402L 2161.42,1372.05 r0 top value=49.9
R61 "CRCW040249R9FKED" 0402L 2161.42,1336.61 r0 top value=49.9
R62 "CRCW04020000Z0ED" 0402 2159.45,1783.46 r0 top value=0
R63 "CRCW04024K87FKED" 0402 2041.34,1488.19 r180 bottom value=4.87k
R64 "CRCW040210K0JNED" 0402 2000,1210.63 r0 bottom value=10k
R65 "CRCW04020000Z0ED" 0402 2000,1250 r180 bottom value=0
R66 "HVC2010-1M0GT3" 2010 2496.06,1255.91 r0 bottom value=1.00Meg
R67 "CRCW04022K49FKED" 0402L 1816.93,1307.09 r270 bottom value=2.49k
R68 "CRCW04022K49FKED" 0402L 1852.36,1307.09 r270 bottom value=2.49k
R69 "CRCW04022K40JNED" 0402 2072.83,1606.3 r270 top value=2.4k
R70 "CRCW04020000Z0ED" 0402 1927.17,1633.86 r90 top value=0
R71 "CRCW04020000Z0ED" 0402L 1801.18,1403.54 r0 top value=0
R72 "CRCW04022K49FKED" 0402L 1781.5,1307.09 r90 bottom value=2.49k
R73 "CRCW04020000Z0ED" 0402L 1801.18,1438.98 r0 top value=0
R74 "CRCW04020000Z0ED" 0402L 1830.71,1549.21 r180 bottom value=0
R75 "CRCW04022K49FKED" 0402L 1879.92,1385.83 r270 bottom value=2.49k
R76 "CRCW040210K0JNED" 0402L 2092.52,2143.7 r0 top value=10k
R77 "CRCW04020000Z0ED" 0402 464.57,1509.84 r0 top value=0
R78 "CRCW0402165KFKED" 0402 433.07,1415.35 r90 bottom value=165k
R79 "CRCW0402200KFKED" 0402 472.44,1415.35 r270 bottom value=200k
R80 "CRCW06032R00JNEA" 0603 312.99,1047.24 r0 top value=2.0
R81 "CRCW04020000Z0ED" 0402 82.68,929.13 r0 bottom value=0
R82 "CRCW0402301KFKED" 0402 94.49,1202.76 r180 bottom value=301k
R83 "CRCW04020000Z0ED" 0402 271.65,832.68 r0 top value=0
R84 "CRCW04020000Z0ED" 0402 476.38,659.45 r180 top value=0
R85 "CRCW04024K99FKED" 0402 379.92,659.45 r0 top value=4.99k
R86 "CRCW0402200KFKED" 0402 94.49,1242.13 r0 bottom value=200k
R87 "CRCW04022K00FKED" 0402 78.74,832.68 r0 top value=2.00k
R88 "CRCW04021K00FKED" 0402 78.74,746.06 r180 top value=1.00k
R89 "CRCW04020000Z0ED" 0402 464.57,1029.53 r0 top value=0
R90 "CRCW0402432KFKED" 0402 387.8,1086.61 r270 bottom value=432k
R91 "CRCW04022K00FKED" 0402 78.74,659.45 r180 top value=2.00k
R92 "CRCW040295K3FKED" 0402 346.46,1086.61 r90 bottom value=95.3k
R93 "CRCW04020000Z0ED" 0402 57.09,1246.06 r270 top value=0
R94 "CRCW04020000Z0ED" 0402 94.49,1466.54 r0 bottom value=0
R95 "CRCW04021K00FKED" 0402 78.74,572.83 r180 top value=1.00k
R96 "CRCW0402162KFKED" 0402 94.49,1387.8 r180 bottom value=162k
R97 "CRCW0402200KFKED" 0402 94.49,1348.43 r0 bottom value=200k
R98 "CRCW04020000Z0ED" 0402 208.66,1466.54 r180 bottom value=0
R99 "CRCW0402162KFKED" 0402 326.77,1427.17 r180 bottom value=162k
R100 "CRCW0402200KFKED" 0402 326.77,1364.17 r0 bottom value=200k
R101 "CRCW0402100KJNED" 0402 135.83,1246.06 r90 top value=100k
R102 "CRCW04020000Z0ED" 0402 96.46,1246.06 r90 top value=0
R103 "CRCW040210K0JNED" 0402L 1484.25,401.57 r180 bottom value=10k
R104 "CRCW040210K0JNED" 0402L 1744.09,401.57 r0 bottom value=10k
R105 "CRCW040210K0JNED" 0402L 1484.25,437.01 r180 bottom value=10k
R106 "CRCW040210K0JNED" 0402L 1744.09,437.01 r0 bottom value=10k
R107 "CRCW040210K0JNED" 0402L 1484.25,472.44 r180 bottom value=10k
R108 "CRCW040210K0JNED" 0402L 1744.09,472.44 r0 bottom value=10k
R109 "CRCW040210K0JNED" 0402L 1484.25,507.87 r180 bottom value=10k
R110 "CRCW040210K0JNED" 0402L 1744.09,507.87 r0 bottom value=10k
R111 "CRCW040210K0JNED" 0402L 1484.25,543.31 r180 bottom value=10k
R112 "CRCW040210K0JNED" 0402L 1744.09,543.31 r0 bottom value=10k
R113 "CRCW040210K0JNED" 0402L 1484.25,578.74 r180 bottom value=10k
R114 "CRCW040210K0JNED" 0402L 1744.09,578.74 r0 bottom value=10k
R115 "CRCW040210K0JNED" 0402L 1484.25,614.17 r180 bottom value=10k
R116 "CRCW040210K0JNED" 0402L 1744.09,614.17 r0 bottom value=10k
R117 "CRCW040210K0JNED" 0402L 1484.25,649.61 r180 bottom value=10k
R118 "CRCW040210K0JNED" 0402L 1744.09,649.61 r0 bottom value=10k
